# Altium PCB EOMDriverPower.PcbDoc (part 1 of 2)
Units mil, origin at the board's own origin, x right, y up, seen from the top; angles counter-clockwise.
Board outline 6400 x 9100 mil, 6 copper layers (Top Layer, GND1, PWR1, PWR2, GND2, Bottom Layer); 300 components, 184 nets, 876 pads, 174 vias.
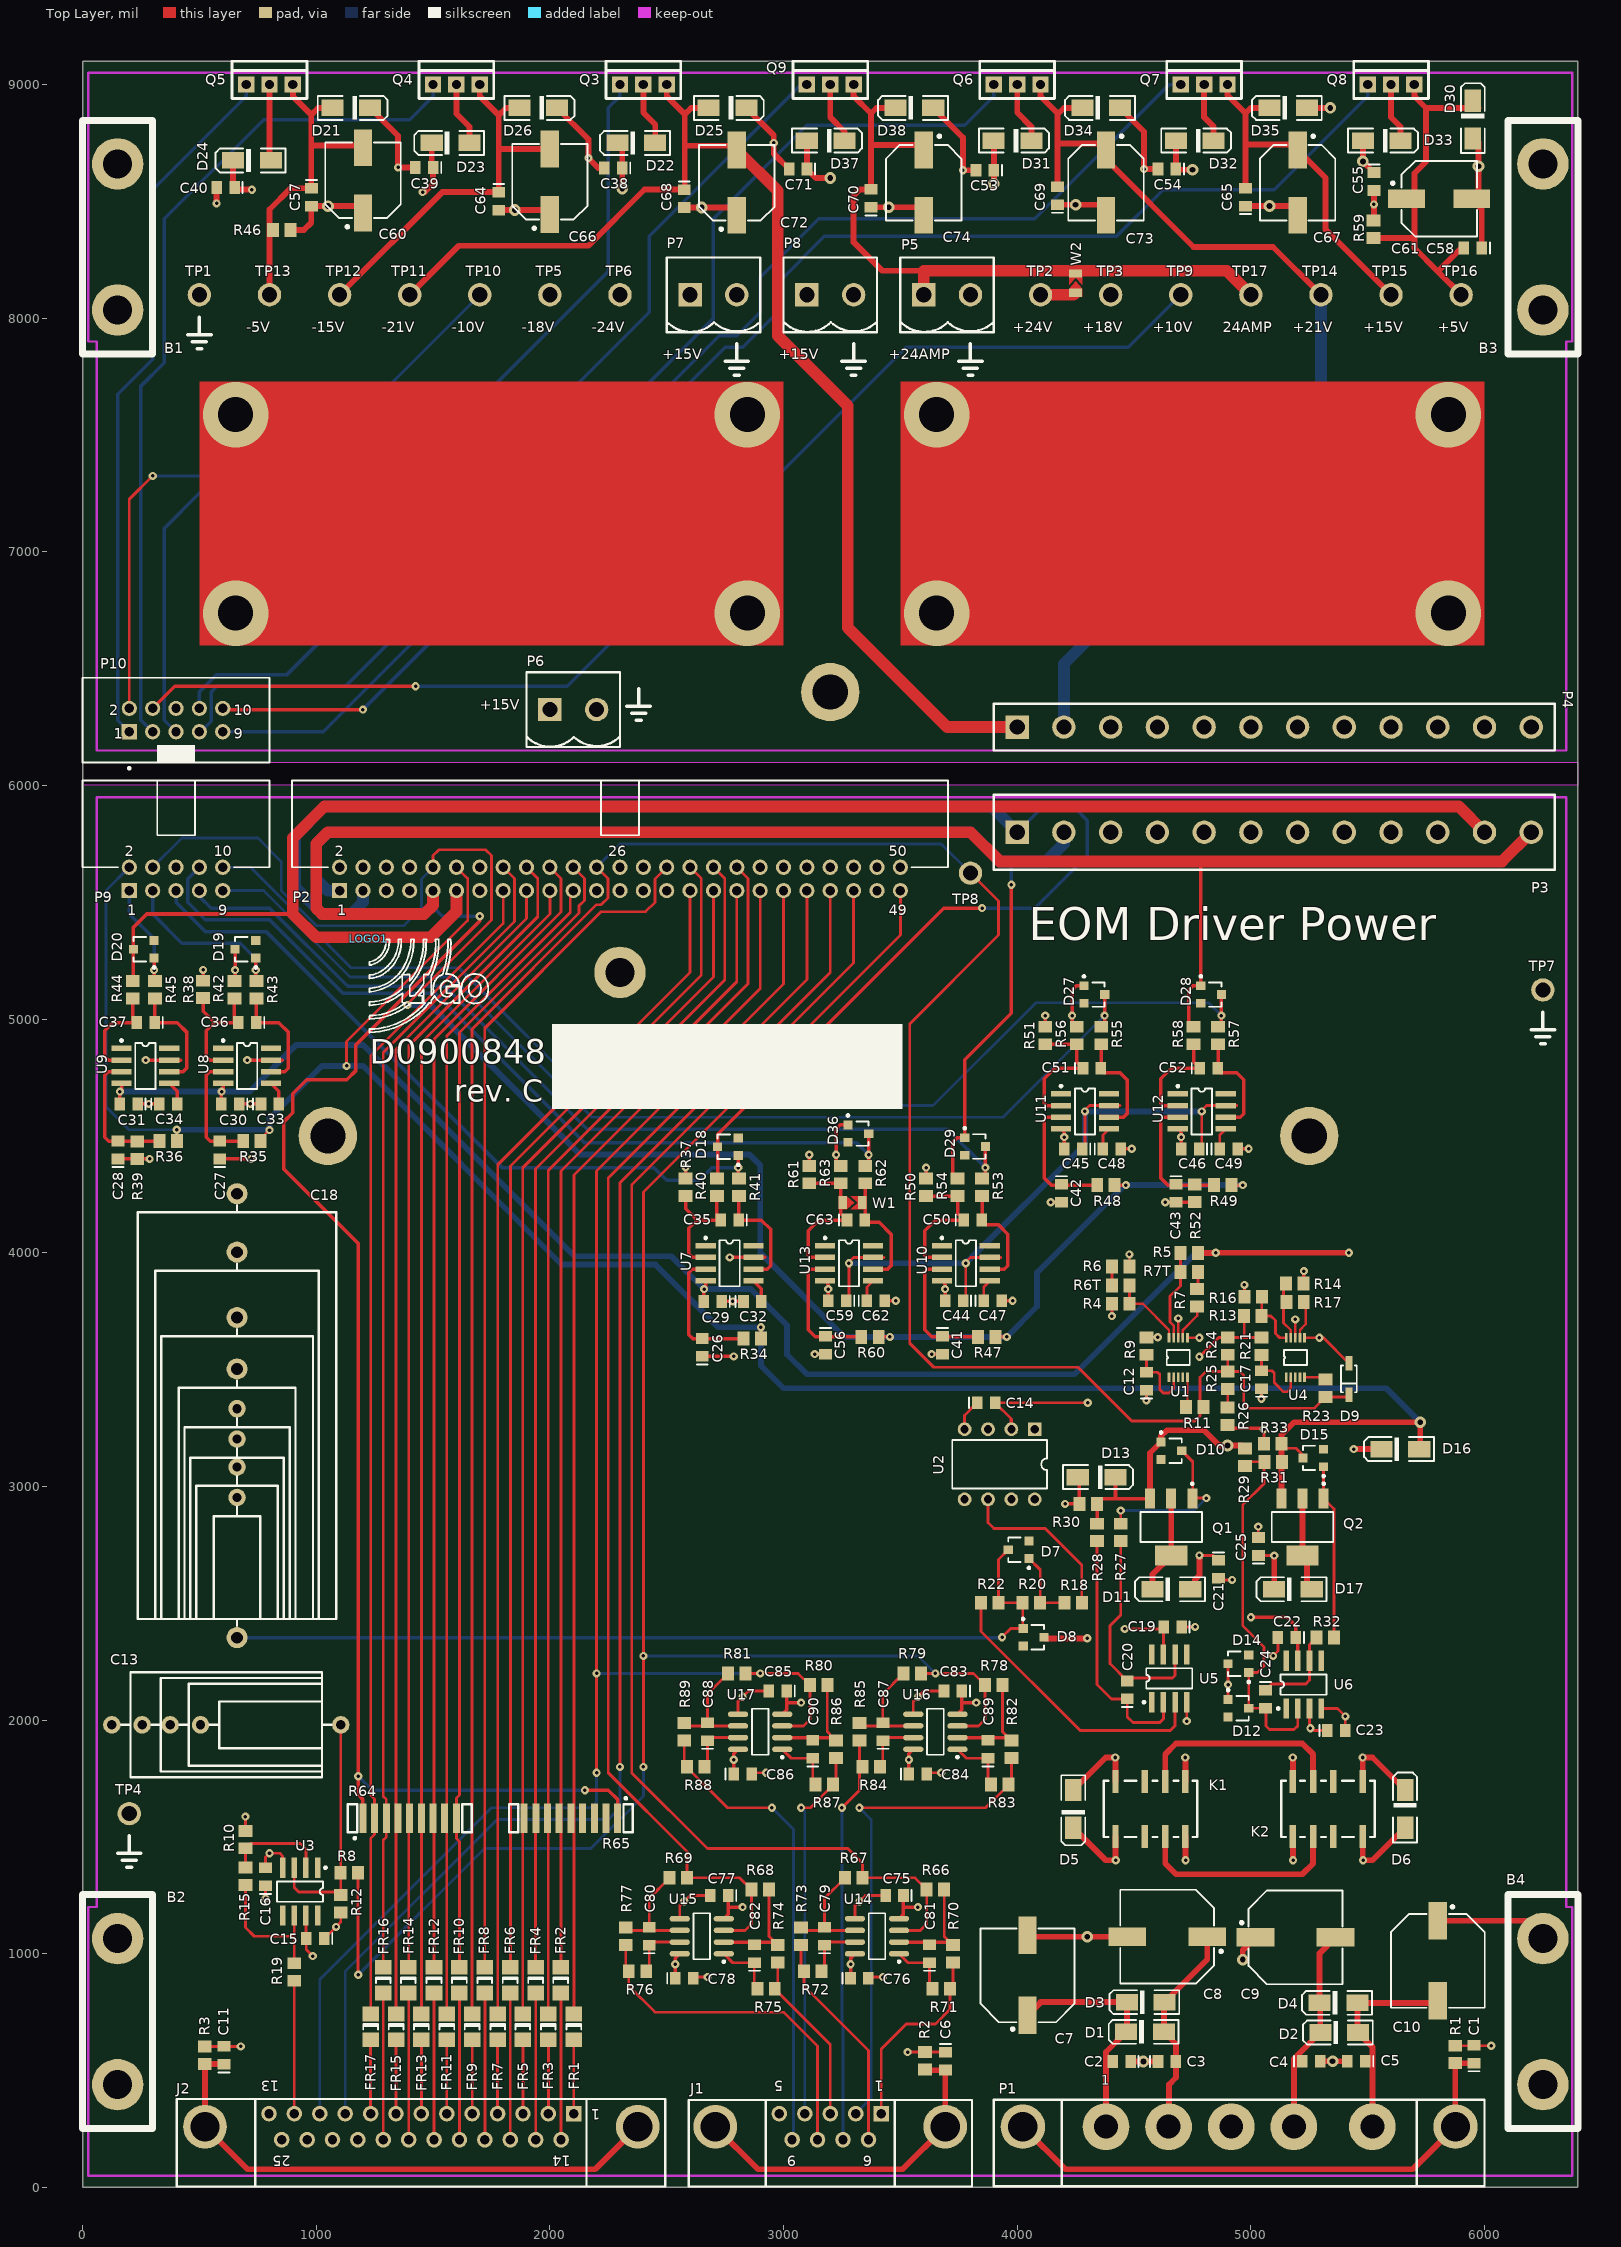
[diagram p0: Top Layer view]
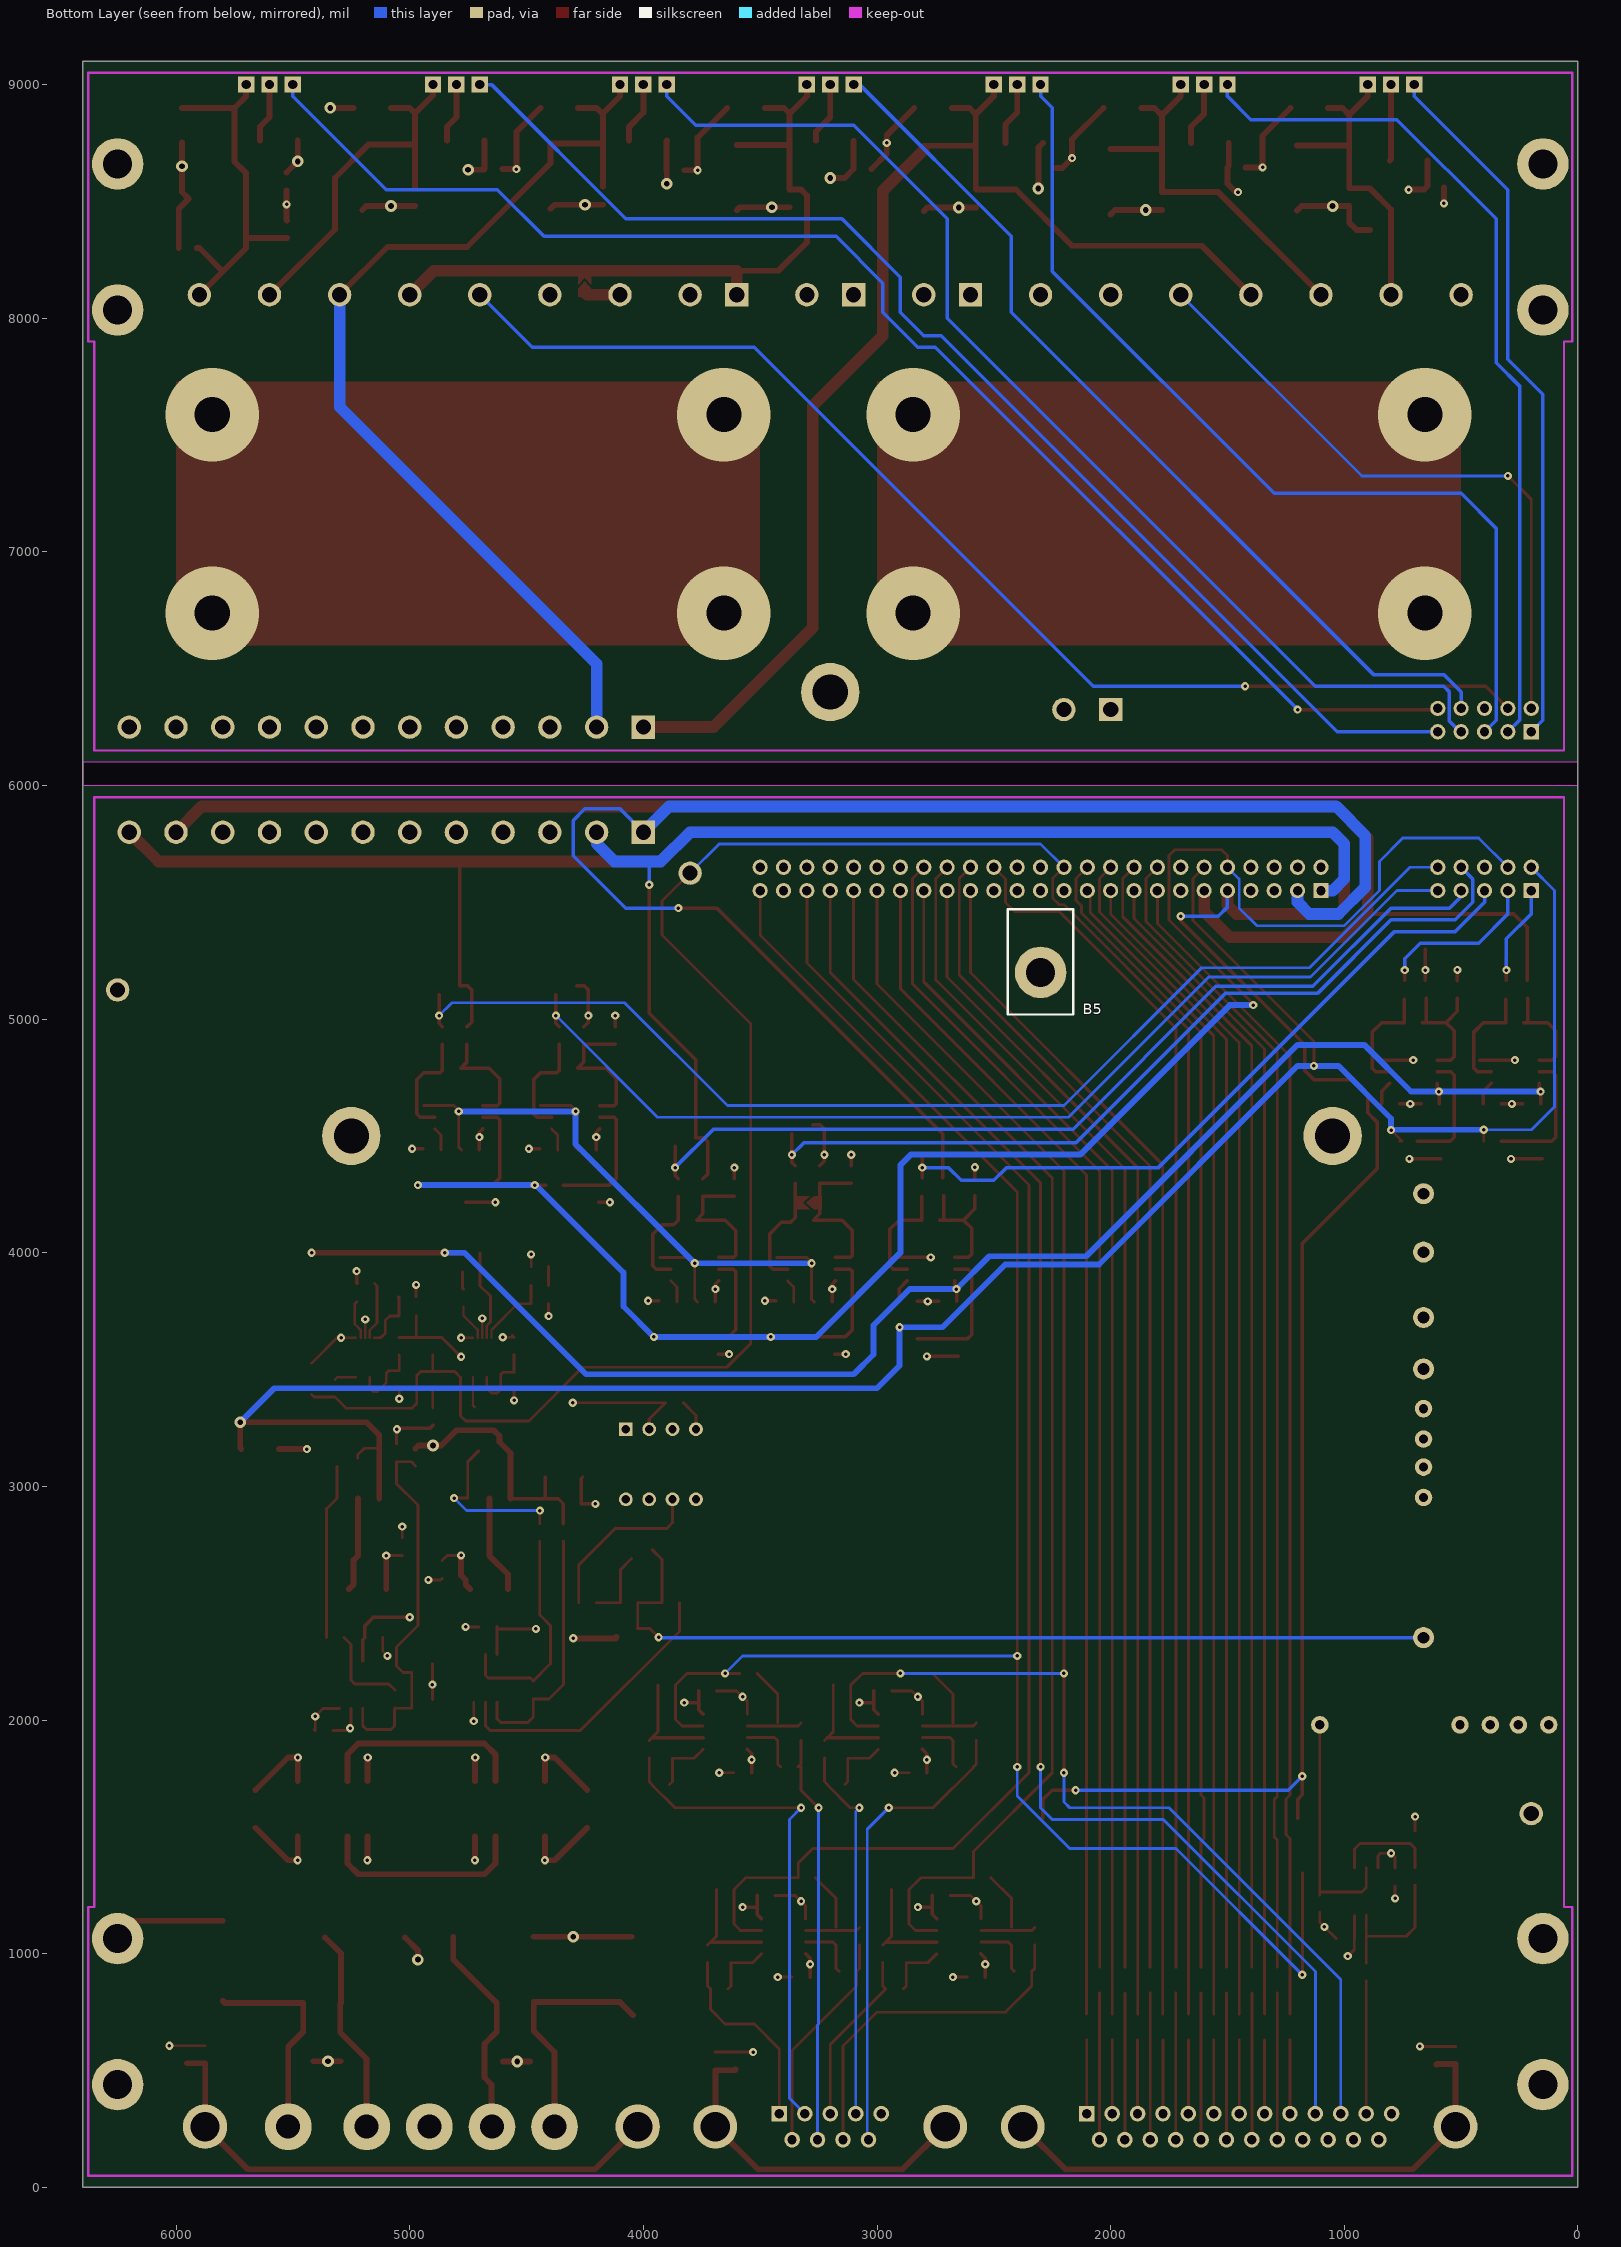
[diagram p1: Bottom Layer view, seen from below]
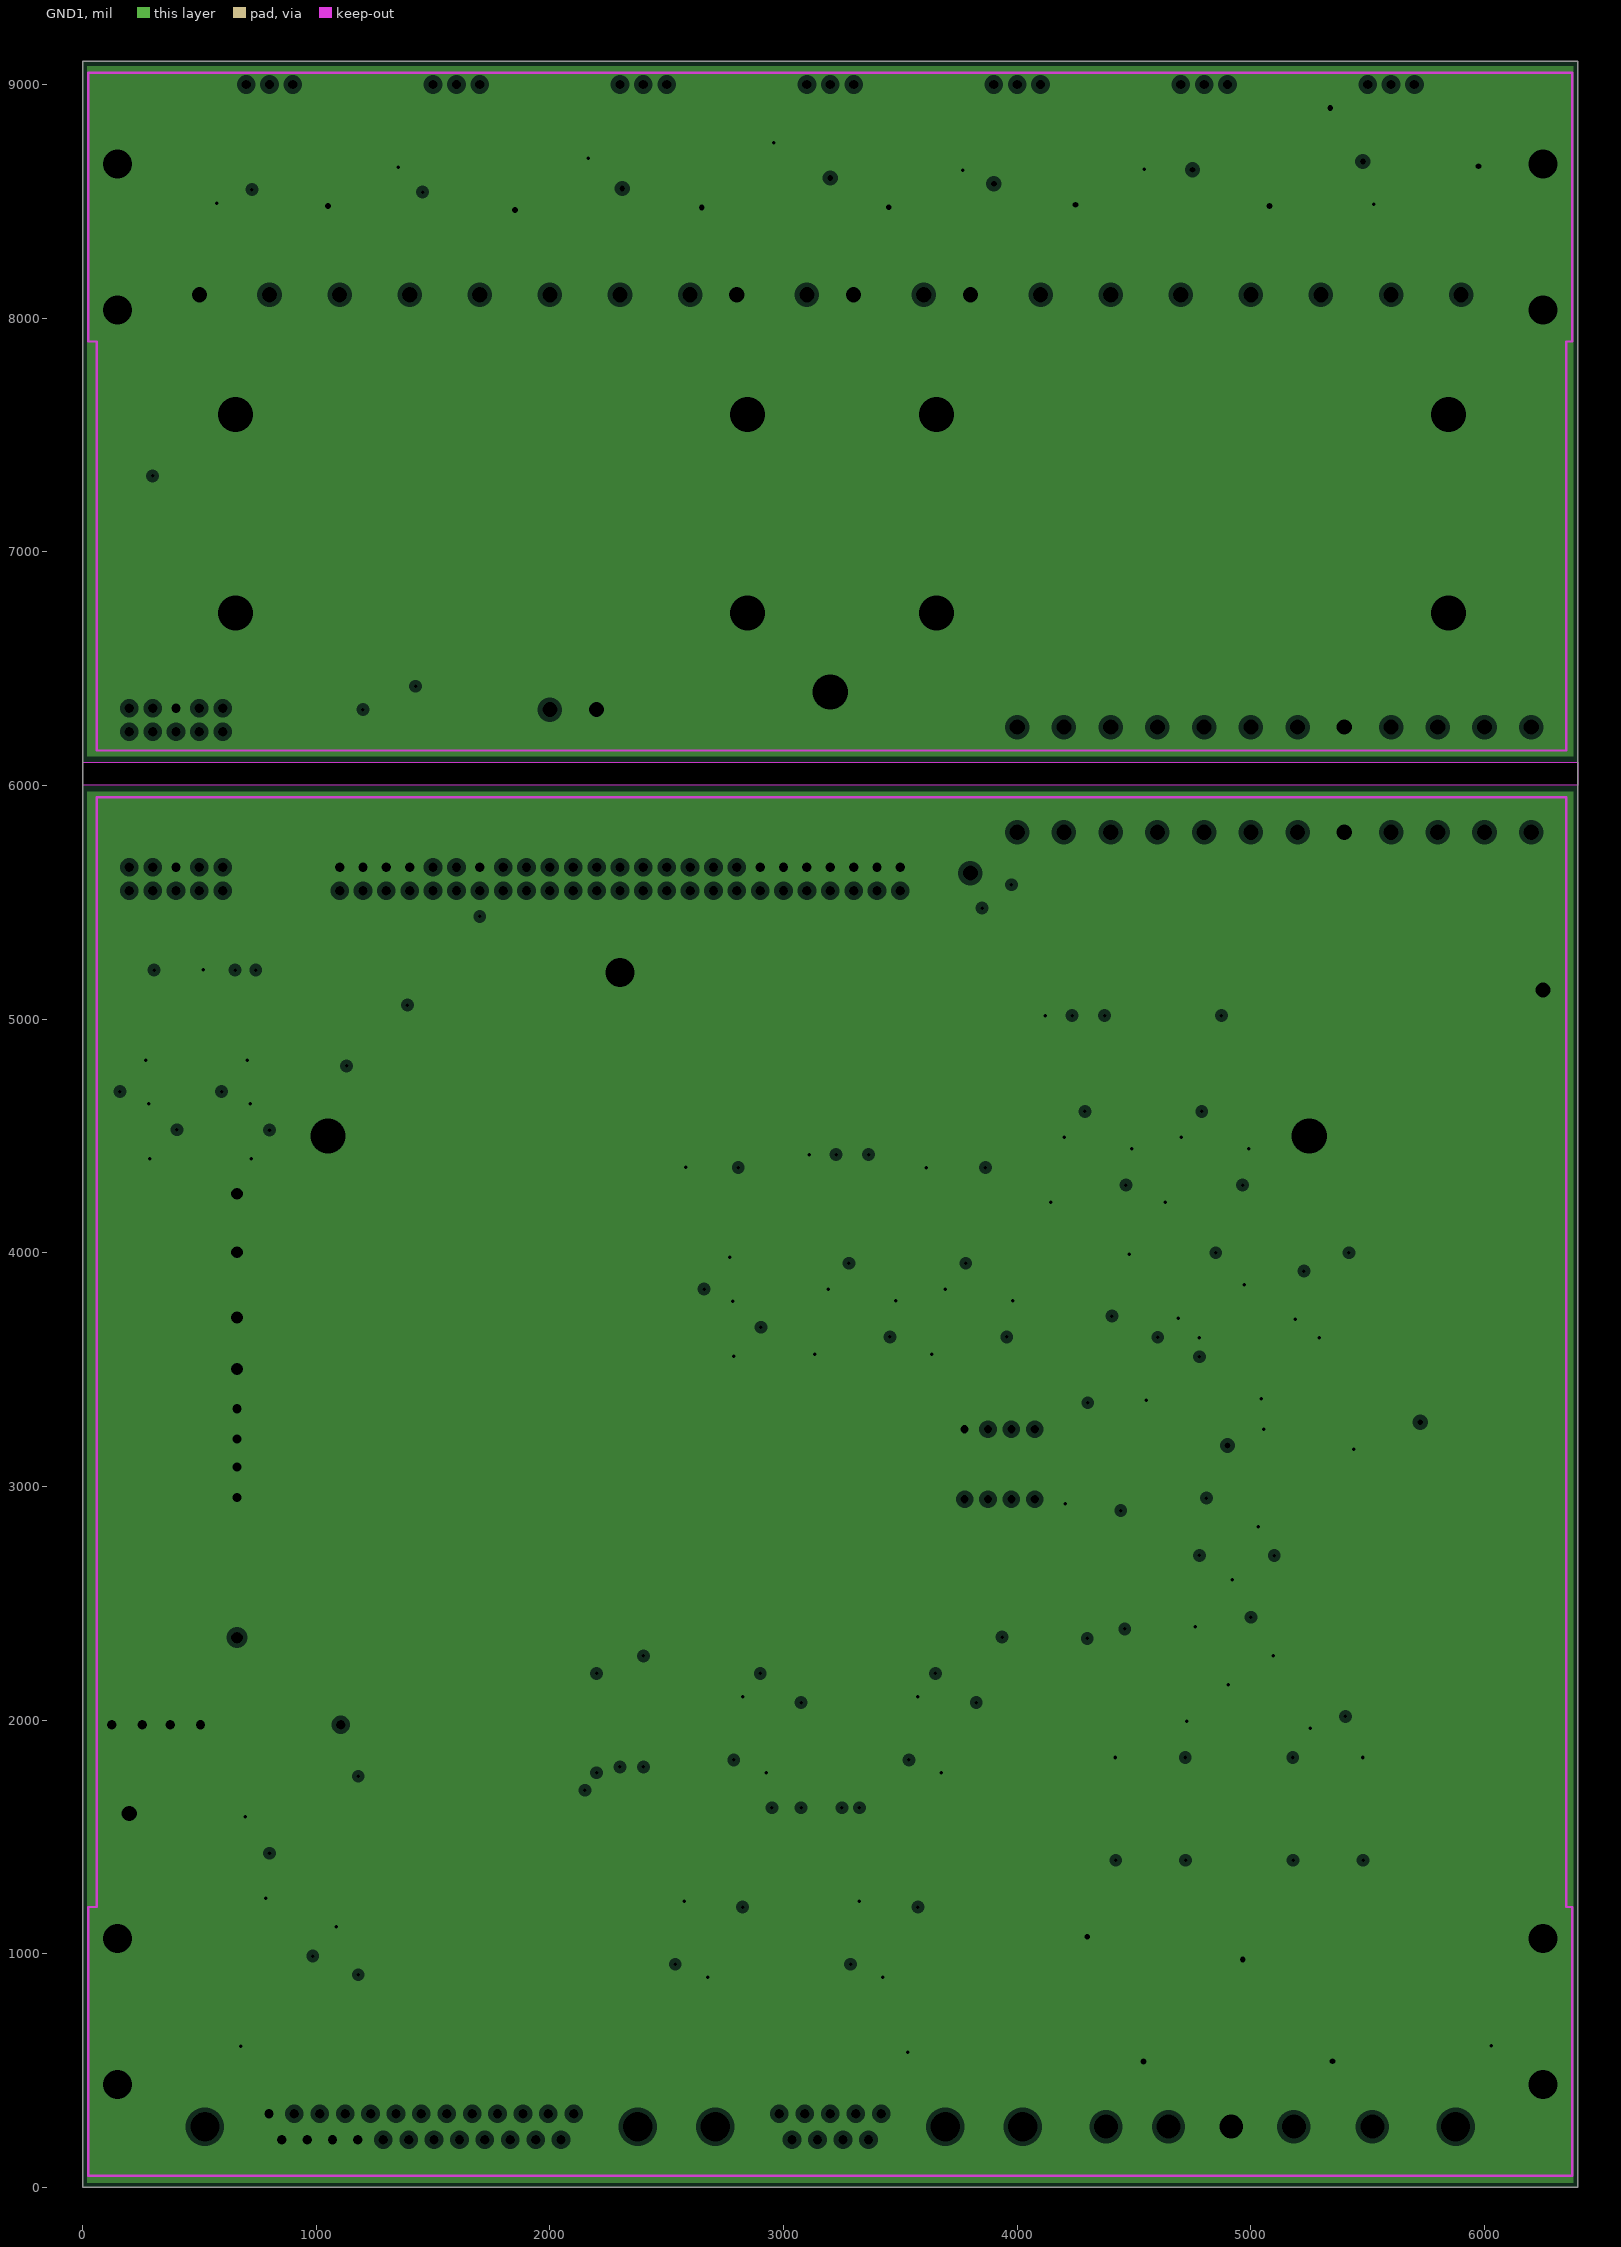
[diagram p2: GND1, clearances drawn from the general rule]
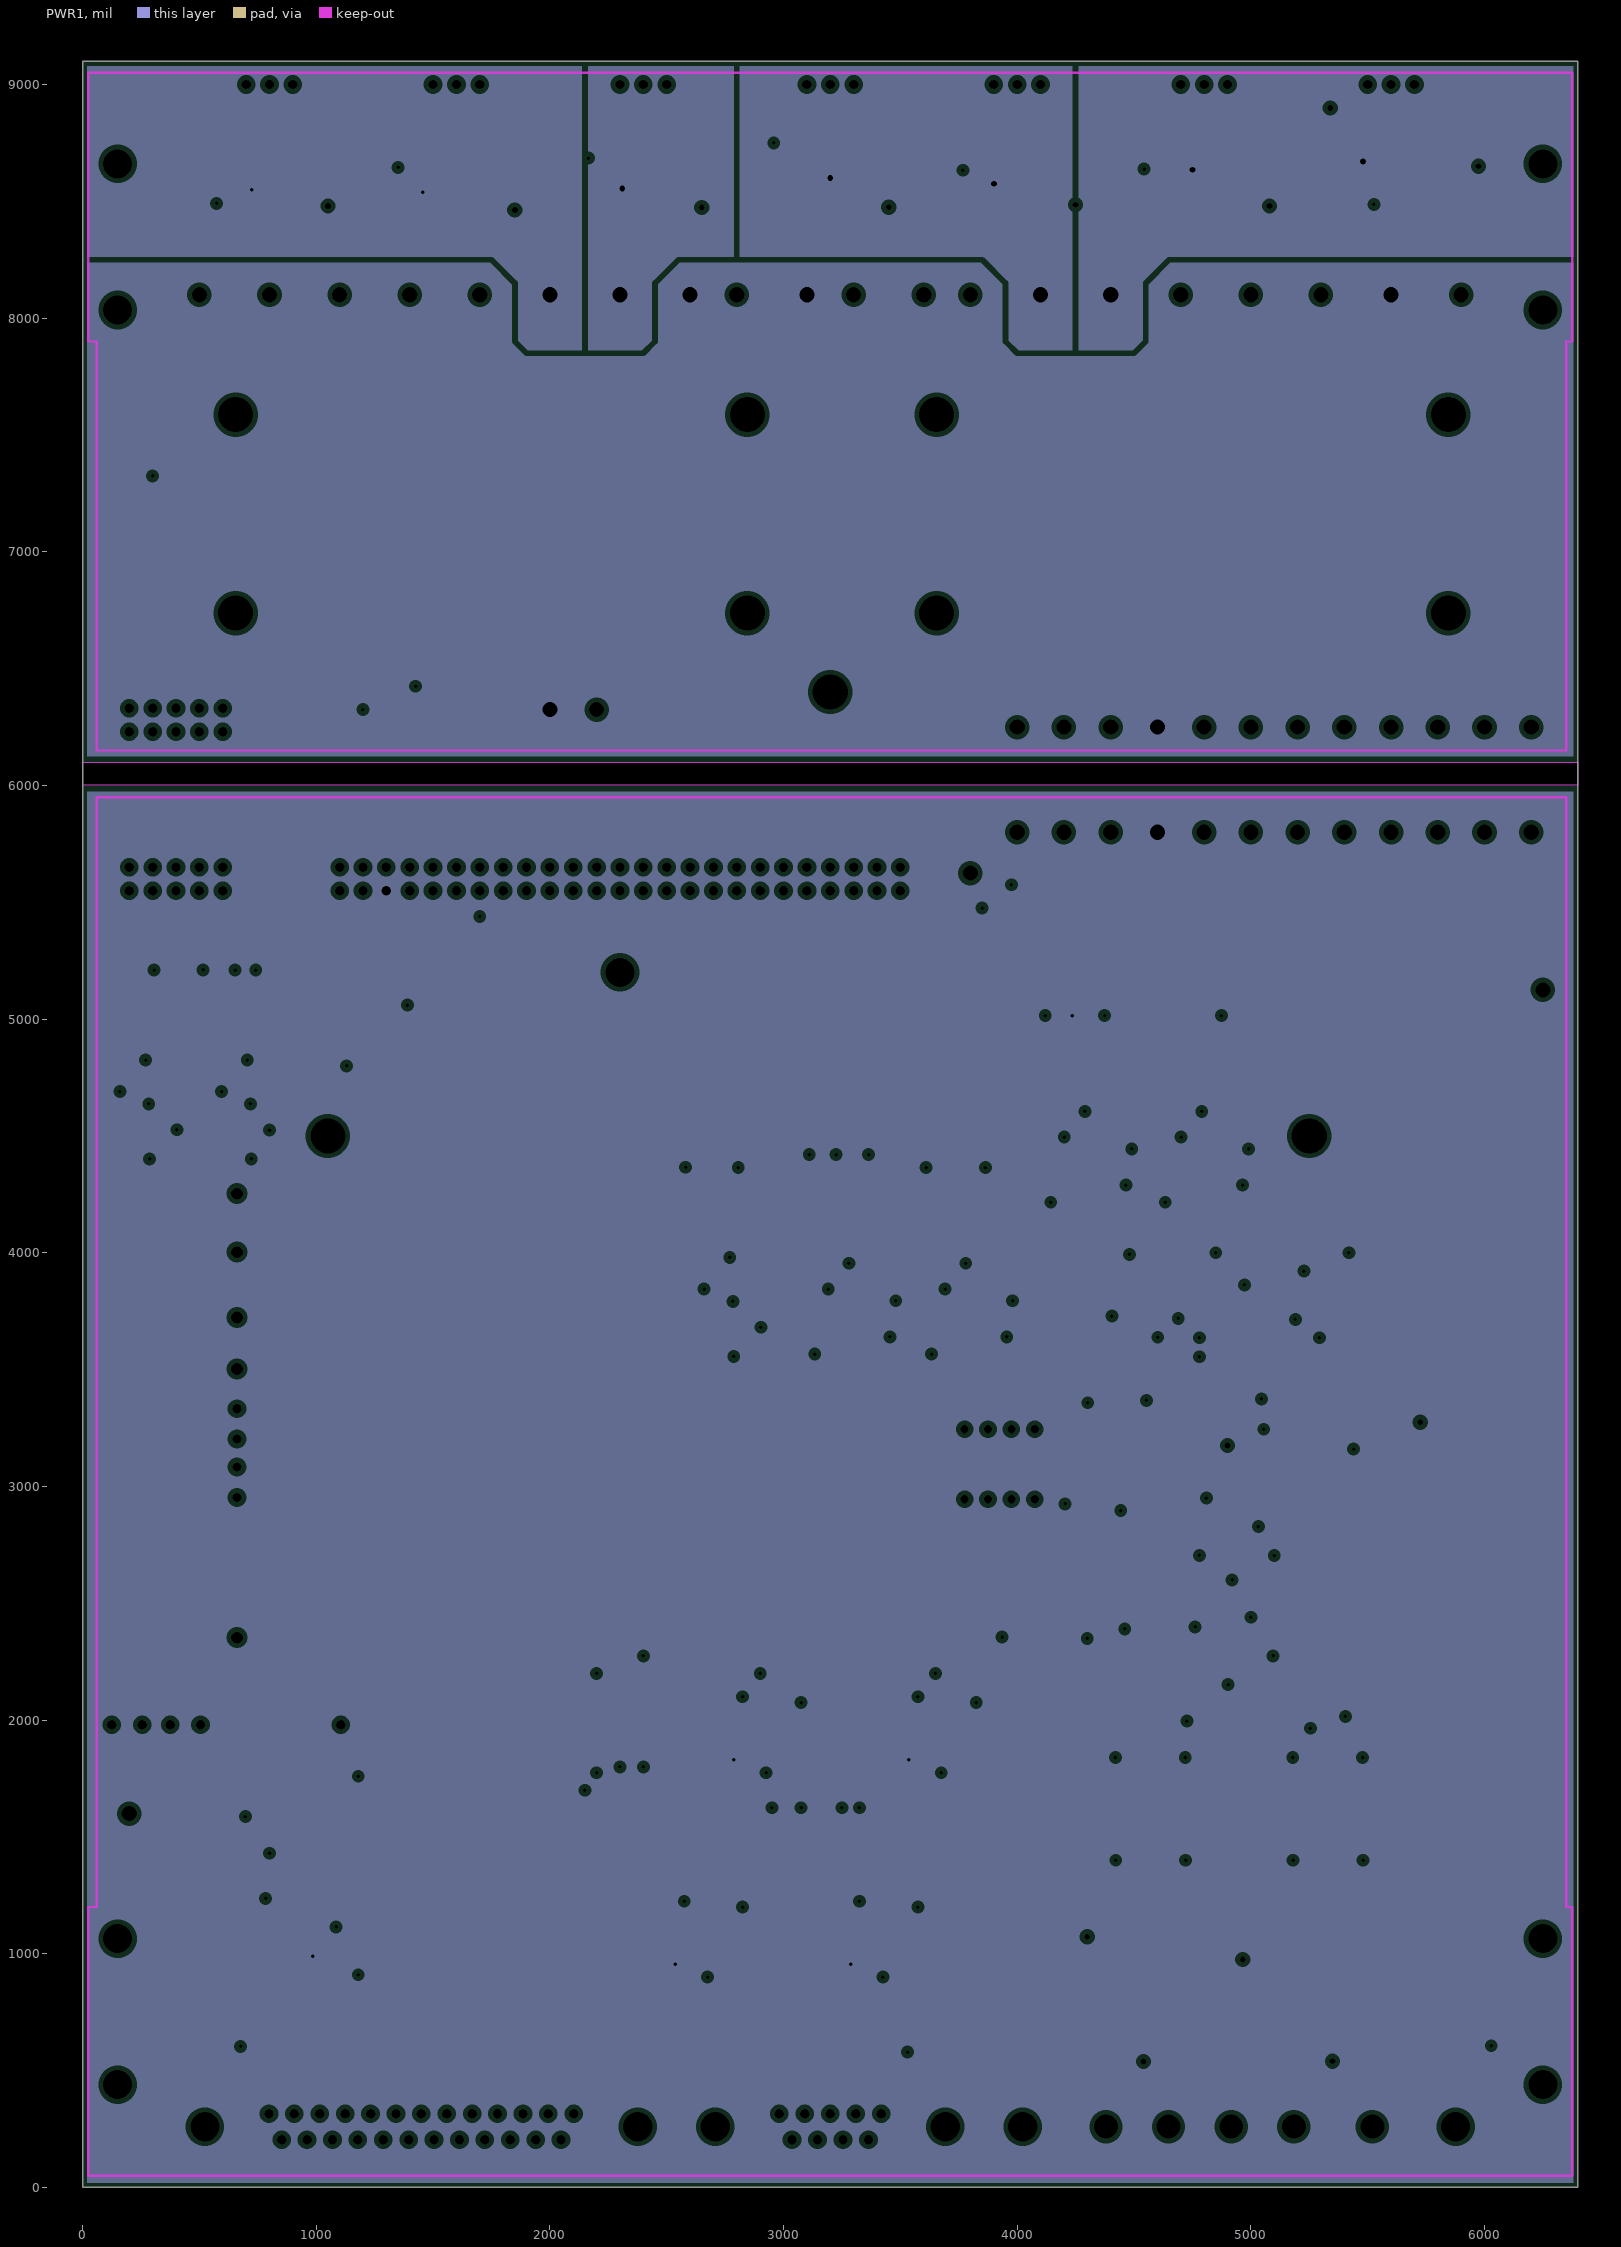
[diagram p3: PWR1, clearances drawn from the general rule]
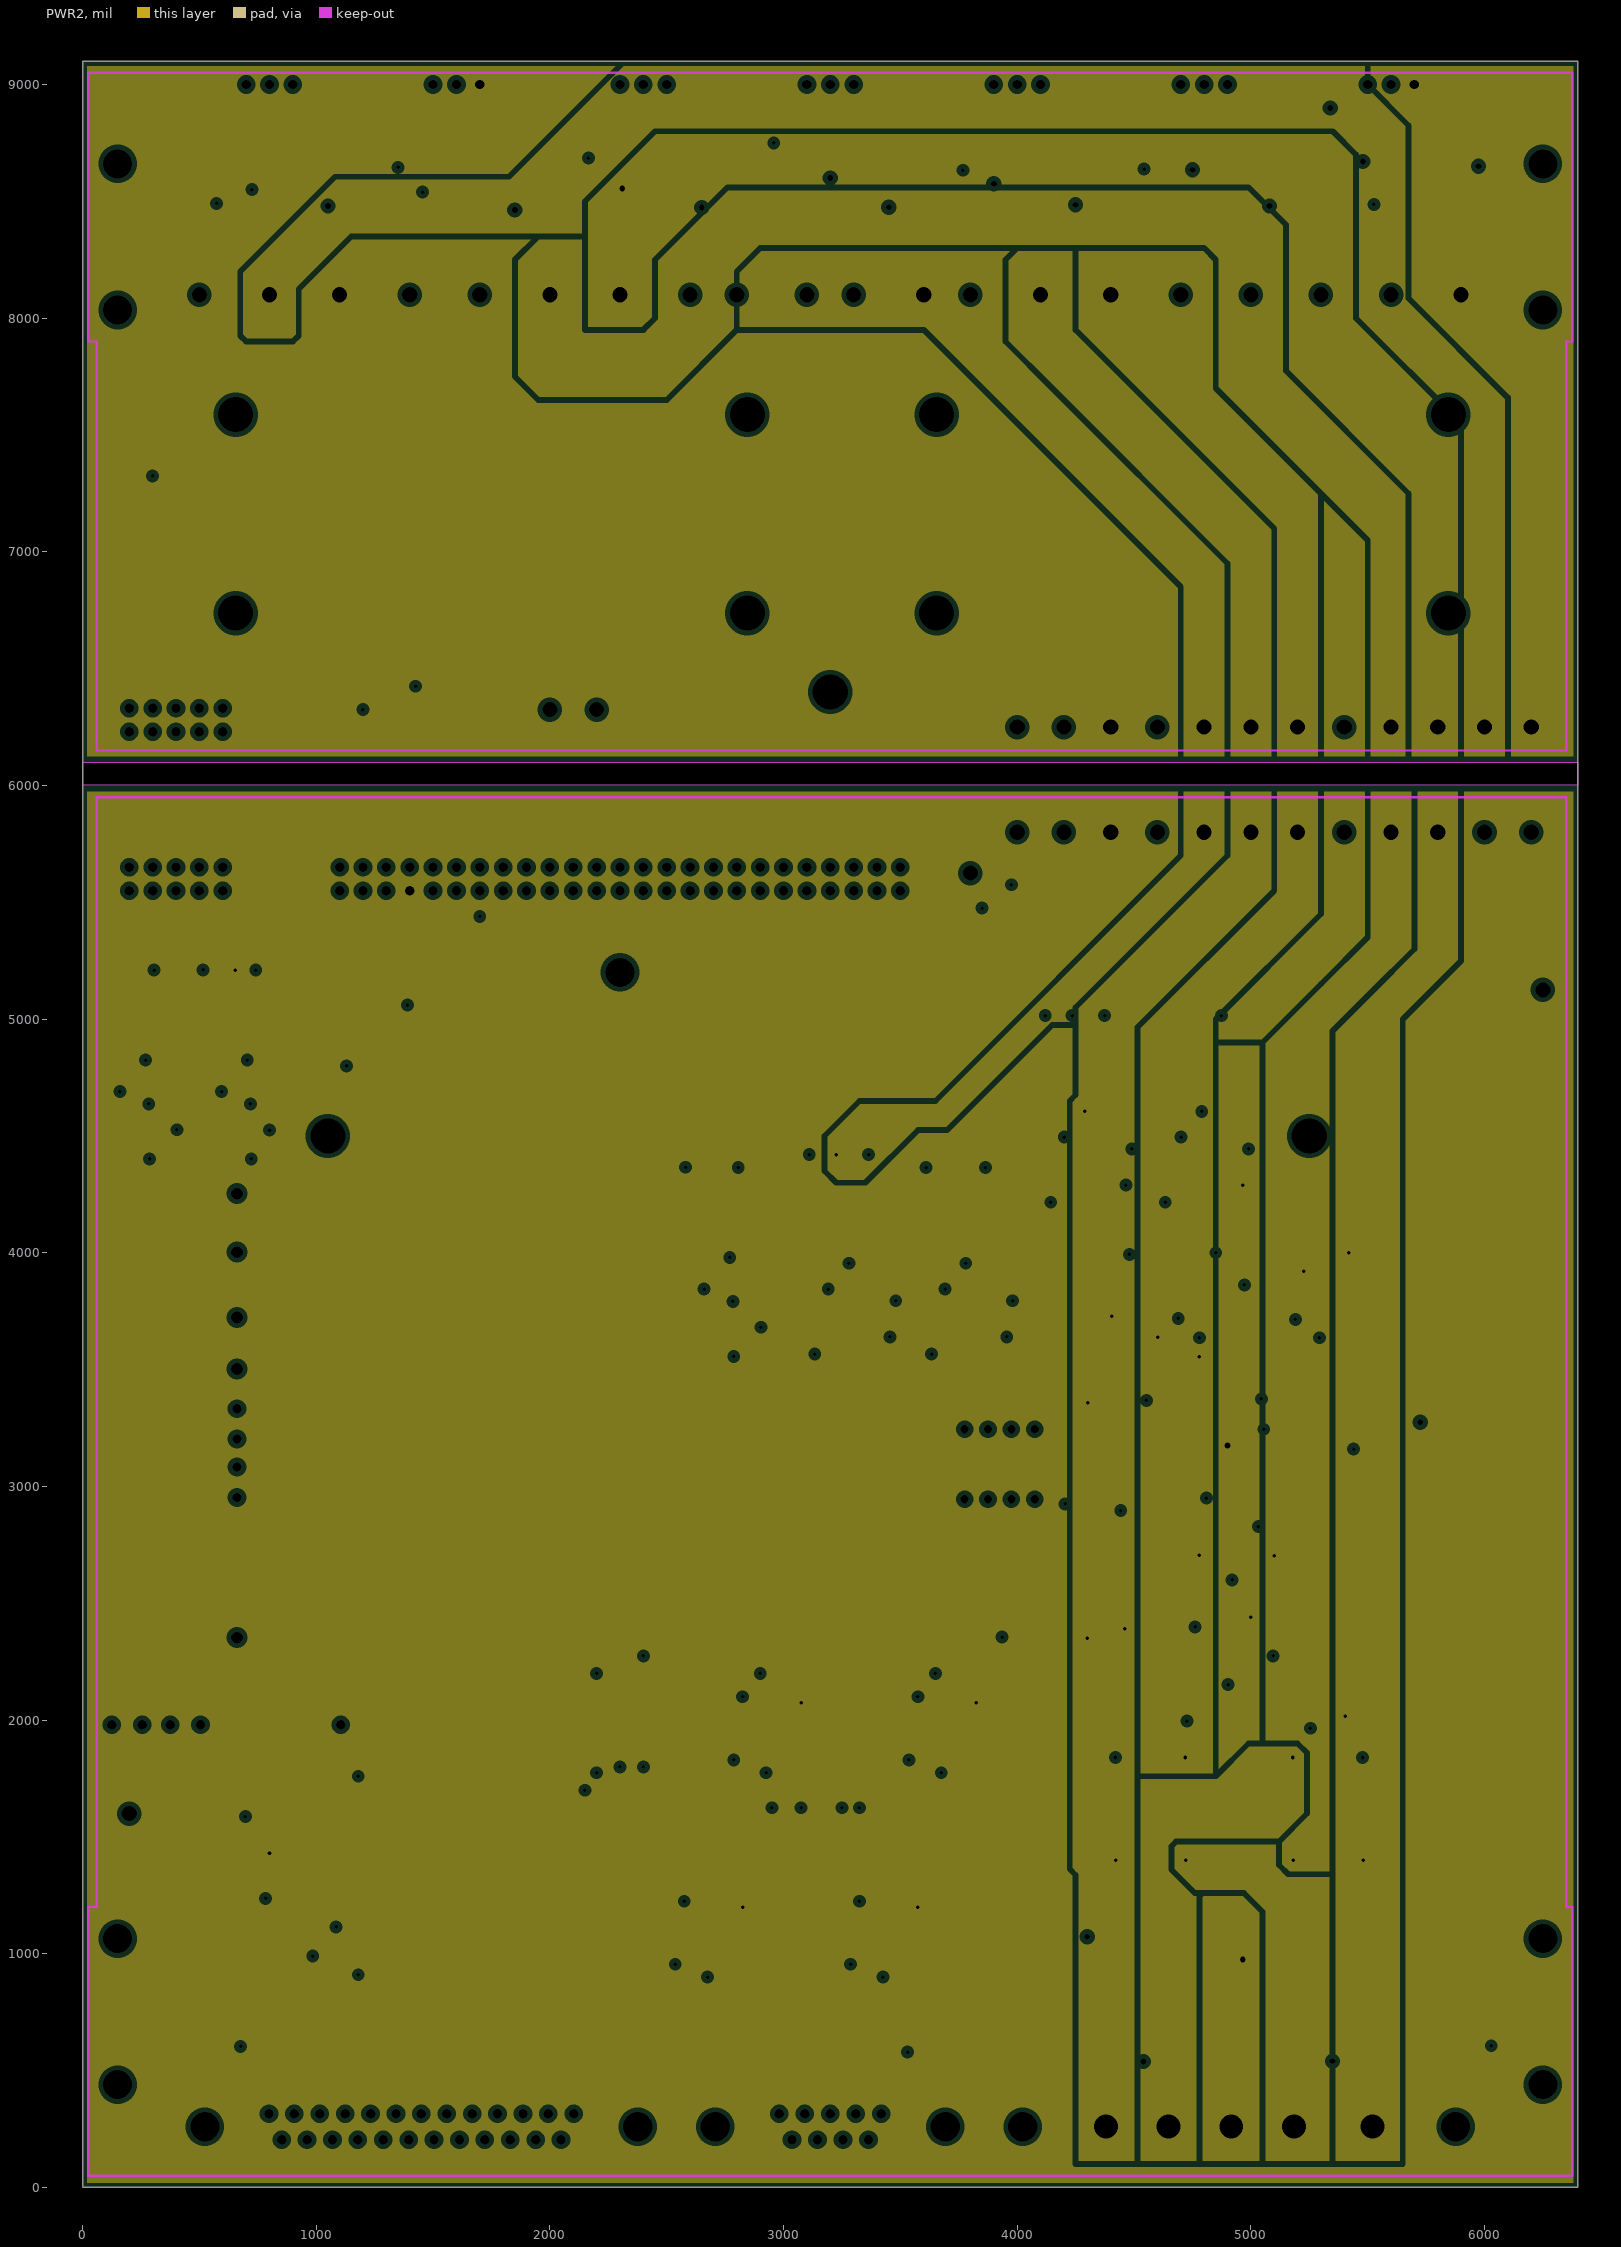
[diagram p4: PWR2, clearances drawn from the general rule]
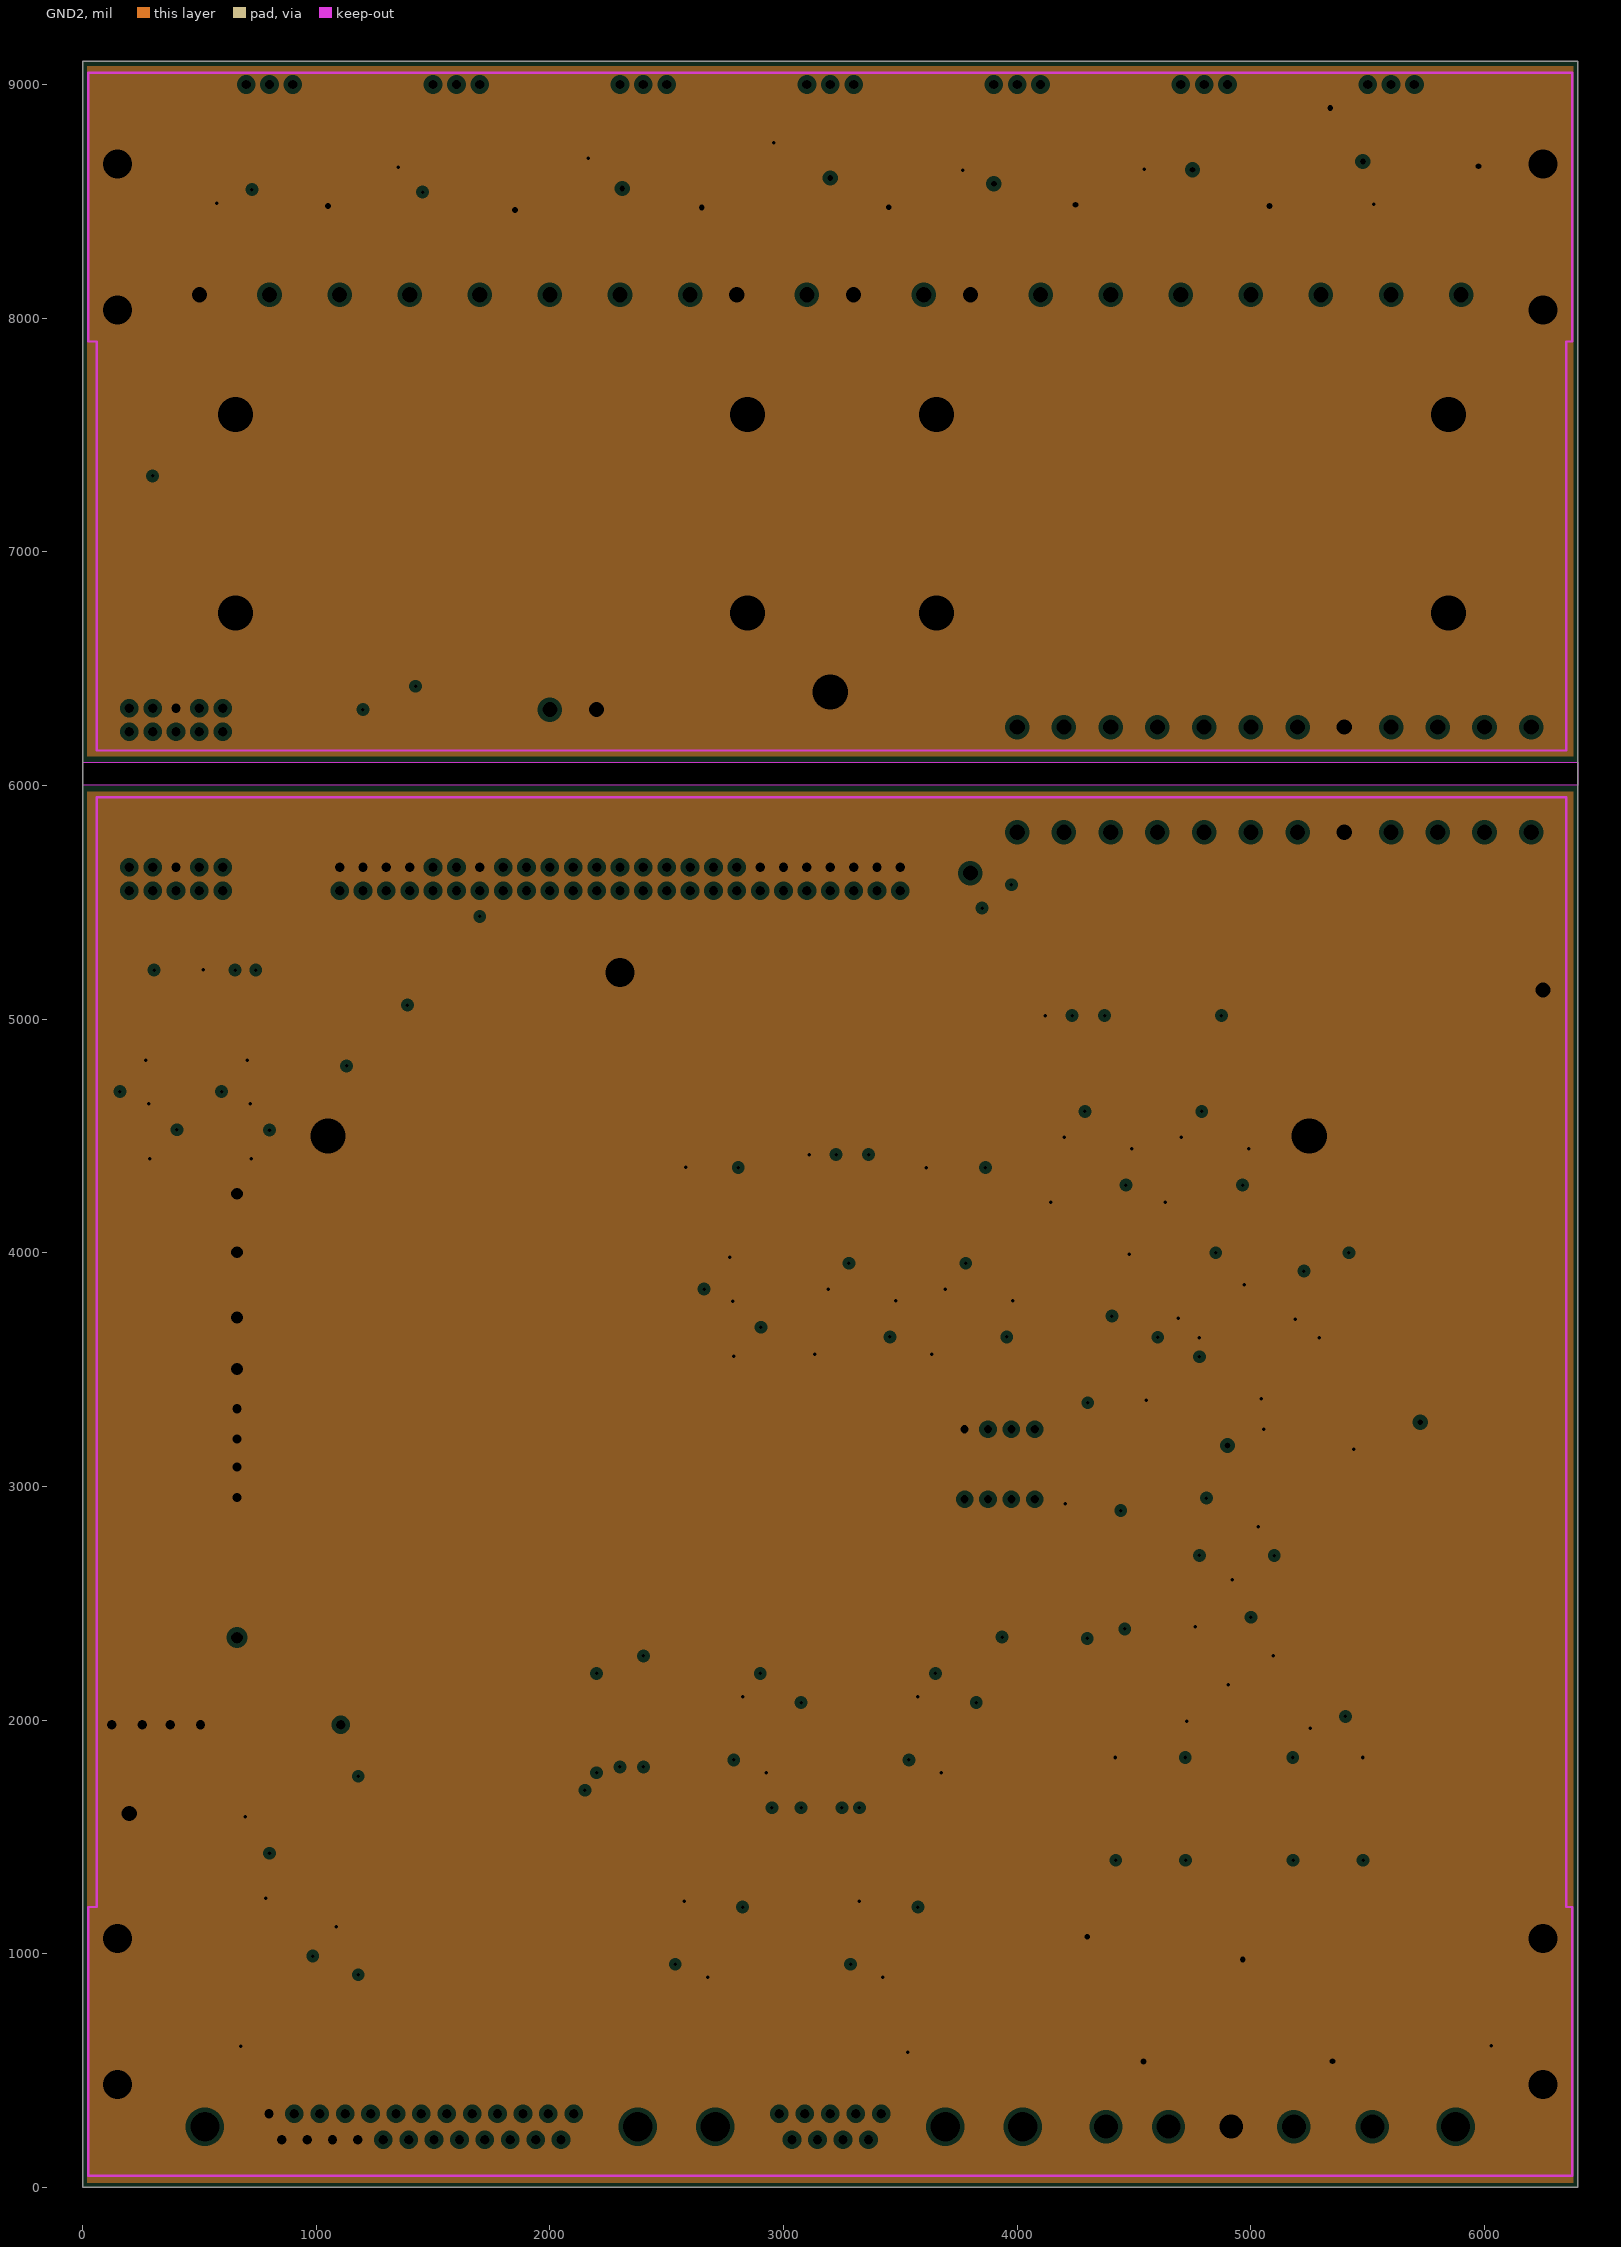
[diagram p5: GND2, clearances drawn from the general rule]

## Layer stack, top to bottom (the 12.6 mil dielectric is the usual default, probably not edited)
Top Solder: solder mask 0.4, Solder Resist, Dk 3.5
Top Layer: signal copper 1.4
Dielectric1: core 12.6, FR-4, Dk 4.8
GND1: plane copper 1.4
Dielectric2: prepreg 12.6, FR-4, Dk 4.8
PWR1: plane copper 1.4
Dielectric4: core 12.6, FR-4, Dk 4.8
PWR2: plane copper 1.4
Dielectric5: prepreg 12.6, FR-4, Dk 4.8
GND2: plane copper 1.4
Dielectric3: core 12.6, FR-4, Dk 4.8
Bottom Layer: signal copper 1.4
Bottom Solder: solder mask 0.4, Solder Resist, Dk 3.5

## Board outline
0,0 0,9100 6400,9100 6400,0
cut-out: 0,6000 0,6100 6400,6100 6400,6000

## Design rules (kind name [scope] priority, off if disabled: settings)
Clearance Clearance_1 [(HasFootprint('MSOP10'))] p1: gap=8
Clearance [All] p2: gap=9.68
FabricationTestPointUsage TestPointUsage [All] p1: valid=0 allowmultiple=FALSE
FabricationTestpoint Testpoint [All] p1: side=3 testpointundercomponent=TRUE minsize=40 maxsize=100 preferedsize=60 minholesize=0 maxholesize=40 preferedholesize=32 testpointgrid=1 allowsidetop=TRUE allowsidebottom=TRUE usegrid=TRUE gridtolerance=0.01
HoleSize [All] p1: absolutevalues=TRUE maxlimit=250 minlimit=15 maxpercent=80.000 minpercent=20.000
MinimumAnnularRing MinimumAnnularRingPad [IsPad] p1: minimumring=12
MinimumAnnularRing [All] p2: minimumring=10
MinimumSolderMaskSliver [All] p1: minsoldermaskwidth=5
PlaneClearance [All] p1: clearance=20
PlaneConnect [All] p1: planeconnectstyle=Relief reliefexpansion=20 reliefentries=4 reliefconductorwidth=10 reliefairgap=10
PolygonConnect [All] p1: connectstyle=Relief reliefconductorwidth=10 reliefentries=4 polygonreliefangle="90 Angle" airgapwidth=10
RoutingVias [All] p1: holewidth=15 width=35 viastyle="Through Hole" minholewidth=15 minwidth=35 maxholewidth=150 maxwidth=400
SilkToSilkClearance [All] p1: silktosilkclearance=8
SilkToSolderMaskClearance SilkscreenOverComponentPads [IsPad] p1: minsilkscreentomaskgap=0 clearancetoexposedcopper=TRUE
SolderMaskExpansion [All] p1: expansion=4
Width [All] p1: maxlimit=100 minlimit=8 preferedwidth=10
22 further rules are at their usual default settings.

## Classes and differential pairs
component class EOMDriverPower3: C6 C11 C13 C15 C16 C75 C76 C77 C78 C79 C80 C81 C82 C83 C84 C85 C86 C87 C88 C89 C90 FR1 FR2 FR3 FR4 FR5 FR6 FR7 FR8 FR9 FR10 FR11 FR12 FR13 FR14 FR15 FR16 FR17 J1 J2 P2 R2 R3 R8 R10 R12 R15 R19 R64 R65 R66 R67 R68 R69 R70 R71 R72 R73 R74 R75 R76 R77 R78 R79 R80 R81 R82 R83 R84 R85 R86 R87 R88 R89 U3 U14 U15 U16 U17
component class EOMDriverPower1: B1 B2 B3 B4 C1 C2 C3 C4 C5 C7 C8 C9 C10 C12 C14 C17 C18 C19 C20 C21 C22 C23 C24 C25 D1 D2 D3 D4 D5 D6 D7 D8 D9 D10 D11 D12 D13 D14 D15 D16 D17 E1 E2 E3 H1 H2 H3 H4 H5 H6 H7 H8 H9 H10 H11 H12 H13 K1 K2 LOGO1 P1 P3 P4 Q1 Q2 R1 R4 R5 R6 R6T R7 R7T R9 R11 R13 R14 R16 R17 R18 R20 R21 R22 R23 R24 R25 R26 R27 R28 R29 R30 R31 R32 R33 TP1 TP2 TP3 TP4 TP5 TP6 TP7 TP8 TP9 TP10 U1 U2 U4 U5 U6
component class EOMDriverPower2: C26 C27 C28 C29 C30 C31 C32 C33 C34 C35 C36 C37 C38 C39 C40 C41 C42 C43 C44 C45 C46 C47 C48 C49 C50 C51 C52 C53 C54 C55 C56 C57 C58 C59 C60 C61 C62 C63 C64 C65 C66 C67 C68 C69 C70 C71 C72 C73 C74 D18 D19 D20 D21 D22 D23 D24 D25 D26 D27 D28 D29 D30 D31 D32 D33 D34 D35 D36 D37 D38 P5 P6 P7 P8 P9 P10 Q3 Q4 Q5 Q6 Q7 Q8 Q9 R34 R35 R36 R37 R38 R39 R40 R41 R42 R43 R44 R45 R46 R47 R48 R49 R50 R51 R52 R53 R54 R55 R56 R57 R58 R59 R60 R61 R62 R63 TP11 TP12 TP13 TP14 TP15 TP16 TP17 U7 U8 U9 U10 U11 U12 U13 W1 W2

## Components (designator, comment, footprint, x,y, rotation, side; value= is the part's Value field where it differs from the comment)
B1 "Bracket" Bracket-RA_708 150,8660 r180 top locked
B2 "Bracket" Bracket-RA_708 150,440 r0 top locked
B3 "Bracket" Bracket-RA_708 6250,8660 r180 top locked
B4 "Bracket" Bracket-RA_708 6250,440 r0 top locked
C1 "100n" CC2013-0805 5955,570 r90 top
C2 "100n" CC2013-0805 4447,539 r180 top
C3 "100n" CC2013-0805 4641,539 r0 top
C4 "100n" CC2013-0805 5258,540 r0 top
C5 "100n" CC2013-0805 5451,540 r180 top
C6 "100n" CC2013-0805 3693,541 r270 top
C7 "100u" AC103-041/G 4044,908 r90 top
C8 "100u" AC103-041/G 4642,1073 r180 top
C9 "100u" AC103-041/G 5191,1070 r0 top
C10 "100u" AC103-041/G 5800,970 r270 top
C11 "100n" CC2013-0805 605,565 r90 top
C12 "100n" CC2013-0805 4553,3450 r90 top
C13 "1u" CA-ALL4 1105,1980 r180 top
C14 "100n" CC2013-0805 3867,3358 r0 top
C15 "100n" CC2013-0805 996,1065 r180 top
C16 "100n" CC2013-0805 783,1329 r90 top
C17 "100n" CC2013-0805 5045,3457 r90 top
C18 "20u" CA-ALL8 661,2353 r90 top
C19 "100n" CC2013-0805 4665,2399 r180 top
C20 "100p" CC2013-0805 4471,2129 r90 top
C21 "100n" CC2013-0805 4861,2645 r270 top
C22 "100n" CC2013-0805 5154,2353 r180 top
C23 "100n" CC2013-0805 5366,1956 r0 top
C24 "470p" CC2013-0805 5063,2090 r270 top
C25 "100n" CC2013-0805 5032,2743 r90 top
C26 "100n" CC2013-0805 2652,3595 r90 top
C27 "100n" CC2013-0805 587,4440 r90 top
C28 "100n" CC2013-0805 152,4440 r90 top
C29 "100n" CC2013-0805 2697,3792 r180 top
C30 "100n" CC2013-0805 632,4637 r180 top
C31 "100n" CC2013-0805 197,4637 r180 top
C32 "68p" CC2013-0805 2867,3792 r0 top
C33 "68p" CC2013-0805 802,4637 r0 top
C34 "68p" CC2013-0805 367,4637 r0 top
C35 "47p" CC2013-0805 2770,4140 r180 top
C36 "47p" CC2013-0805 705,4985 r180 top
C37 "47p" CC2013-0805 270,4985 r180 top
C38 "100n" CC2013-0805 2271,8643 r180 top
C39 "100n" CC2013-0805 1462,8645 r180 top
C40 "100n" CC2013-0805 612,8559 r180 top
C41 "100n" CC2013-0805 3680,3605 r270 top
C42 "100n" CC2013-0805 4190,4255 r270 top
C43 "100n" CC2013-0805 4680,4255 r270 top
C44 "100n" CC2013-0805 3730,3795 r180 top
C45 "100n" CC2013-0805 4240,4445 r180 top
C46 "100n" CC2013-0805 4740,4445 r180 top
C47 "68p" CC2013-0805 3895,3795 r0 top
C48 "68p" CC2013-0805 4405,4445 r0 top
C49 "68p" CC2013-0805 4905,4445 r0 top
C50 "47p" CC2013-0805 3810,4140 r0 top
C51 "47p" CC2013-0805 4320,4790 r0 top
C52 "47p" CC2013-0805 4820,4790 r0 top
C53 "100n" CC2013-0805 3862,8633 r180 top
C54 "100n" CC2013-0805 4641,8638 r180 top
C55 "100n" CC2013-0805 5527,8585 r270 top
C56 "100n" CC2013-0805 3180,3605 r270 top
C57 "100n" CC2013-0805 979,8518 r270 top
C58 "100n" CC2013-0805 5950,8300 r180 top
C59 "100n" CC2013-0805 3230,3795 r180 top
C60 "330u" AC083-033/F 1200,8590 r90 top
C61 "330u" AC083-033/F 5806,8511 r0 top
C62 "68p" CC2013-0805 3395,3795 r0 top
C63 "47p" CC2013-0805 3310,4140 r0 top
C64 "100n" CC2013-0805 1781,8501 r270 top
C65 "100n" CC2013-0805 4977,8518 r90 top
C66 "100u" AC083-033/F 2000,8584 r90 top
C67 "100u" AC083-033/F 5200,8580 r270 top
C68 "100n" CC2013-0805 2575,8512 r270 top
C69 "100n" CC2013-0805 4172,8524 r90 top
C70 "100n" CC2013-0805 3374,8513 r90 top
C71 "100n" CC2013-0805 3062,8638 r180 top
C72 "100u" AC083-033/F 2800,8580 r90 top
C73 "100u" AC083-033/F 4380,8580 r270 top
C74 "100u" AC083-033/F 3600,8580 r270 top
C75 "100n" CC2013-0805 3475,1250 r180 top
C76 "100n" CC2013-0805 3325,895 r0 top
C77 "100n" CC2013-0805 2725,1250 r180 top
C78 "100n" CC2013-0805 2575,895 r0 top
C79 "33p" CC2013-0805 3175,1075 r90 top
C80 "33p" CC2013-0805 2425,1075 r90 top
C81 "33p" CC2013-0805 3625,1000 r90 top
C82 "33p" CC2013-0805 2875,1000 r90 top
C83 "100n" CC2013-0805 3725,2125 r180 top
C84 "100n" CC2013-0805 3575,1770 r0 top
C85 "100n" CC2013-0805 2975,2125 r180 top
C86 "100n" CC2013-0805 2825,1770 r0 top
C87 "33p" CC2013-0805 3425,1950 r90 top
C88 "33p" CC2013-0805 2675,1950 r90 top
C89 "33p" CC2013-0805 3875,1875 r90 top
C90 "33p" CC2013-0805 3125,1875 r90 top
D1 "shottky diode" DO-SMA 4547,666 r180 top
D2 "shottky diode" DO-SMA 5378,663 r180 top
D3 "shottky diode" DO-SMA 4550,793 r180 top
D4 "shottky diode" DO-SMA 5375,790 r180 top
D5 "shottky diode" DO-SMA 4240,1620 r270 top
D6 "shottky diode" DO-SMA 5660,1620 r90 top
D7 "BAS16" SO-G3/C2.25 4006,2729 r90 top
D8 "BAS16" SO-G3/C2.25 4070,2355 r270 top
D9 "zener diode" DO-SOD123 5420,3460 r270 top
D10 "BAS16" SO-G3/C2.25 4660,3153 r270 top
D11 "shottky diode" DO-SMA 4660,2560 r180 top
D12 "BAS16" SO-G3/C2.25 4947,2051 r270 top
D13 "shottky diode" DO-SMA 4340,3040 r0 top
D14 "BAS16" SO-G3/C2.25 4947,2241 r90 top
D15 "BAS16" SO-G3/C2.25 5267,3122 r90 top
D16 "shottky diode" DO-SMA 5640,3160 r180 top
D17 "shottky diode" DO-SMA 5180,2560 r180 top
D18 "BAS16" SO-G3/C2.25 2762,4454 r90 top
D19 "BAS16" SO-G3/C2.25 697,5299 r90 top
D20 "BAS16" SO-G3/C2.25 262,5299 r90 top
D21 "shottky diode" DO-SMA 1150,8900 r0 top
D22 "shottky diode" DO-SMA 2370,8750 r180 top
D23 "shottky diode" DO-SMA 1575,8750 r180 top
D24 "shottky diode" DO-SMA 725,8675 r180 top
D25 "shottky diode" DO-SMA 2760,8900 r0 top
D26 "shottky diode" DO-SMA 1950,8900 r0 top
D27 "BAS16" SO-G3/C2.25 4330,5105 r270 top
D28 "BAS16" SO-G3/C2.25 4830,5105 r270 top
D29 "BAS16" SO-G3/C2.25 3820,4455 r270 top
D30 "shottky diode" DO-SMA 5950,8850 r90 top
D31 "shottky diode" DO-SMA 3980,8760 r0 top
D32 "shottky diode" DO-SMA 4760,8760 r0 top
D33 "shottky diode" DO-SMA 5560,8760 r0 top
D34 "shottky diode" DO-SMA 4360,8900 r180 top
D35 "shottky diode" DO-SMA 5160,8900 r180 top
D36 "BAS16" SO-G3/C2.25 3320,4510 r270 top
D37 "shottky diode" DO-SMA 3180,8760 r0 top
D38 "shottky diode" DO-SMA 3560,8900 r180 top
FR1 "BLM31PG121" CC3216-1206 2103,687 r270 top
FR2 "BLM31PG121" CC3216-1206 2046,887 r270 top
FR3 "BLM31PG121" CC3216-1206 1993,687 r270 top
FR4 "BLM31PG121" CC3216-1206 1939,887 r270 top
FR5 "BLM31PG121" CC3216-1206 1884,687 r270 top
FR6 "BLM31PG121" CC3216-1206 1830,887 r270 top
FR7 "BLM31PG121" CC3216-1206 1777,687 r270 top
FR8 "BLM31PG121" CC3216-1206 1721,887 r270 top
FR9 "BLM31PG121" CC3216-1206 1667,687 r270 top
FR10 "BLM31PG121" CC3216-1206 1613,887 r270 top
FR11 "BLM31PG121" CC3216-1206 1559,687 r270 top
FR12 "BLM31PG121" CC3216-1206 1504,887 r270 top
FR13 "BLM31PG121" CC3216-1206 1450,687 r270 top
FR14 "BLM31PG121" CC3216-1206 1394,887 r270 top
FR15 "BLM31PG121" CC3216-1206 1342,687 r270 top
FR16 "BLM31PG121" CC3216-1206 1287,887 r270 top
FR17 "BLM31PG121" CC3216-1206 1233,687 r270 top
J1 "DB9F" DB9F-RA 3200,260 r180 top locked
J2 "DB25F" DB25F-RA 1450,260 r180 top locked
K1 "IM07GR" RELAY_IMG 4720,1720 r270 top
K2 "IM07GR" RELAY_IMG 5180,1520 r90 top
LOGO1 "LIGO logo" LIGO_LOGO 1225,5345 r0 top
P1 "DsubPower" DSUB-PWR5-RAPLUG 4950,260 r270 top locked
P2 "09 18 150 9421" 918550x323 2300,5650 r0 top locked
P3 "TBlock_5.08_12" TBLOCK-5.08-12 5100,5800 r0 top locked
P4 "TBlock_5.08_12" TBLOCK-5.08-12 5100,6250 r0 top locked
P5 "TBlock_5.08_2" TBLOCK-5.08-2 3700,8100 r0 top locked
P6 "TBlock_5.08_2" TBLOCK-5.08-2 2100,6325 r0 top
P7 "TBlock_5.08_2" TBLOCK-5.08-2 2700,8100 r0 top locked
P8 "TBlock_5.08_2" TBLOCK-5.08-2 3200,8100 r0 top locked
P9 "09 18 510 7323" 918510x323 400,5650 r0 top locked
P10 "09 18 510 7323" 918510x324 400,6280 r0 top locked
Q1 "PZT2222A" SOT223 4659,2826 r180 top
Q2 "PZT2907A" SOT223 5221,2826 r180 top
Q3 "D45H11" TO-220V 2300,9000 r0 top locked
Q4 "D45H11" TO-220V 1500,9000 r0 top locked
Q5 "D45H11" TO-220V 700,9000 r0 top locked
Q6 "D44H11" TO-220V 3900,9000 r0 top locked
Q7 "D44H11" TO-220V 4700,9000 r0 top locked
Q8 "D44H11" TO-220V 5500,9000 r0 top locked
Q9 "D44H11" TO-220V 3100,9000 r0 top locked
R1 "10" CR2012-0805 5875,569 r90 top
R2 "10" CR2012-0805 3605,542 r270 top
R3 "10" CR2012-0805 523,566 r90 top
R4 "1M" CR2012-0805 4443,3782 r0 top
R5 "1M" CR2012-0805 4736,3999 r0 top
R6 "22.1K" CR2012-0805 4443,3941 r180 top
R6T "120" CR2012-0805 4443,3860 r0 top
R7 "21.0K" CR2012-0805 4770,3807 r90 top
R7T "274" CR2012-0805 4736,3918 r180 top
R8 "10K" CR2012-0805 1142,1347 r0 top
R9 "10K" CR2012-0805 4553,3601 r90 top
R10 "NL" CR2012-0805 697,1489 r270 top
R11 "10" CR2012-0805 4760,3340 r0 top
R12 "NL" CR2012-0805 1105,1214 r270 top
R13 "1M" CR2012-0805 5009,3730 r180 top
R14 "1M" CR2012-0805 5188,3869 r0 top
R15 "0" CR2012-0805 697,1331 r270 top
R16 "32.4K" CR2012-0805 5010,3812 r0 top
R17 "30.9K" CR2012-0805 5189,3789 r180 top
R18 "680" CR2012-0805 4239,2502 r180 top
R19 "100" CR2012-0805 906,922 r90 top
R20 "10K" CR2012-0805 4061,2502 r180 top
R21 "10K" CR2012-0805 5046,3600 r90 top
R22 "100" CR2012-0805 3883,2502 r180 top
R23 "10" CR2012-0805 5320,3420 r270 top
R24 "10K" CR2012-0805 4901,3601 r90 top
R25 "2K" CR2012-0805 4901,3455 r90 top
R26 "2K" CR2012-0805 4900,3300 r90 top
R27 "100" CR2012-0805 4443,2803 r90 top
R28 "100" CR2012-0805 4342,2803 r90 top
R29 "2K" CR2012-0805 4975,3125 r270 top
R30 "1K" CR2012-0805 4304,2925 r180 top
R31 "2K" CR2012-0805 5095,3105 r0 top
R32 "100" CR2012-0805 5318,2353 r180 top
R33 "1K" CR2012-0805 5094,3183 r180 top
R34 "499" CR2012-0805 2866,3633 r180 top
R35 "499" CR2012-0805 725,4478 r180 top
R36 "2K" CR2012-0805 366,4478 r180 top
R37 "2K" CR2012-0805 2581,4281 r270 top
R38 "2K" CR2012-0805 516,5127 r270 top
R39 "2K" CR2012-0805 234,4439 r270 top
R40 "2.21K" CR2012-0805 2715,4281 r270 top
R41 "100" CR2012-0805 2810,4280 r270 top
R42 "1K" CR2012-0805 650,5126 r270 top
R43 "100" CR2012-0805 745,5125 r270 top
R44 "499" CR2012-0805 215,5126 r270 top
R45 "100" CR2012-0805 310,5125 r270 top
R46 "2K" CR2012-0805 852,8378 r180 top
R47 "499" CR2012-0805 3870,3640 r180 top
R48 "499" CR2012-0805 4380,4290 r180 top
R49 "2K" CR2012-0805 4880,4290 r180 top
R50 "2K" CR2012-0805 3610,4280 r270 top
R51 "2K" CR2012-0805 4120,4930 r270 top
R52 "2K" CR2012-0805 4760,4255 r270 top
R53 "100" CR2012-0805 3850,4280 r90 top
R54 "2.21K" CR2012-0805 3745,4280 r90 top
R55 "100" CR2012-0805 4360,4930 r90 top
R56 "1K" CR2012-0805 4255,4930 r90 top
R57 "100" CR2012-0805 4860,4930 r90 top
R58 "499" CR2012-0805 4755,4930 r90 top
R59 "2K" CR2012-0805 5525,8381 r90 top
R60 "499" CR2012-0805 3370,3640 r180 top
R61 "2K" CR2012-0805 3110,4335 r270 top
R62 "100" CR2012-0805 3350,4335 r90 top
R63 "NL" CR2012-0805 3245,4335 r90 top
R64 "Resistor array" RES9-1.27ROW 1200,1580 r0 top
R65 "Resistor array" RES9-1.27ROW 2290,1580 r180 top
R66 "4.99K" CR2012-0805 3650,1275 r180 top
R67 "4.99K" CR2012-0805 3300,1325 r0 top
R68 "4.99K" CR2012-0805 2900,1275 r180 top
R69 "4.99K" CR2012-0805 2550,1325 r0 top
R70 "49.9K" CR2012-0805 3725,1000 r90 top
R71 "100" CR2012-0805 3675,850 r180 top
R72 "100" CR2012-0805 3125,925 r0 top
R73 "49.9K" CR2012-0805 3075,1075 r90 top
R74 "49.9K" CR2012-0805 2975,1000 r90 top
R75 "100" CR2012-0805 2925,850 r180 top
R76 "100" CR2012-0805 2375,925 r0 top
R77 "49.9K" CR2012-0805 2325,1075 r90 top
R78 "4.99K" CR2012-0805 3900,2150 r180 top
R79 "4.99K" CR2012-0805 3550,2200 r0 top
R80 "4.99K" CR2012-0805 3150,2150 r180 top
R81 "4.99K" CR2012-0805 2800,2200 r0 top
R82 "4.99K" CR2012-0805 3975,1875 r90 top
R83 "100" CR2012-0805 3925,1725 r180 top
R84 "100" CR2012-0805 3375,1800 r0 top
R85 "4.99K" CR2012-0805 3325,1950 r90 top
R86 "4.99K" CR2012-0805 3225,1875 r90 top
R87 "100" CR2012-0805 3175,1725 r180 top
R88 "100" CR2012-0805 2625,1800 r0 top
R89 "4.99K" CR2012-0805 2575,1950 r90 top
TP1 "Testpoint" TP1 500,8100 r0 top
TP2 "Testpoint" TP1 4100,8100 r0 top
TP3 "Testpoint" TP1 4400,8100 r0 top
TP4 "Testpoint" TP1 200,1600 r0 top
TP5 "Testpoint" TP1 2000,8100 r0 top
TP6 "Testpoint" TP1 2300,8100 r0 top
TP7 "Testpoint" TP1 6250,5125 r0 top
TP8 "Testpoint" TP1 3800,5625 r90 top
TP9 "Testpoint" TP1 4700,8100 r0 top
TP10 "Testpoint" TP1 1700,8100 r0 top
TP11 "Testpoint" TP1 1400,8100 r90 top
TP12 "Testpoint" TP1 1100,8100 r90 top
TP13 "Testpoint" TP1 800,8100 r90 top
TP14 "Testpoint" TP1 5300,8100 r90 top
TP15 "Testpoint" TP1 5600,8100 r90 top
TP16 "Testpoint" TP1 5900,8100 r90 top
TP17 "Testpoint" TP1 5000,8100 r90 top
U1 "LTC2919" MSOP10 4650,3467 r90 top
U2 "LT1021-10" DIP-8 3925,3095 r180 top
U3 "OP27" SO-G8 931,1266 r180 top
U4 "LTC2919" MSOP10 5151,3467 r90 top
U5 "OP27" SO-G8 4651,2179 r0 top
U6 "OP27" SO-G8 5226,2152 r0 top
U7 "AD829JR" SO-G8 2769,3955 r270 top
U8 "AD829JR" SO-G8 704,4800 r270 top
U9 "AD829JR" SO-G8 269,4800 r270 top
U10 "AD829JR" SO-G8 3780,3955 r270 top
U11 "AD829JR" SO-G8 4290,4605 r270 top
U12 "AD829JR" SO-G8 4790,4605 r270 top
U13 "AD829JR" SO-G8 3280,3955 r270 top
U14 "AD8672" SO-8_N 3400,1075 r180 top
U15 "AD8672" SO-8_N 2650,1075 r180 top
U16 "AD8672" SO-8_N 3650,1950 r180 top
U17 "AD8672" SO-8_N 2900,1950 r180 top
W1 "Jumper" JR2013-0805 3295,4215 r0 top
W2 "Jumper" JR2013-0805 4250,8150 r90 top

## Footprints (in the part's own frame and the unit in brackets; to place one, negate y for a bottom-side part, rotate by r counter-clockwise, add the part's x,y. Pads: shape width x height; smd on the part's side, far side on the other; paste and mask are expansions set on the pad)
918510x323 [mm] "Connector; IDC, Low Profile Male Header, Thru-Hole; 10 Position; Right Angle; Pitch 2.54 mm; Body 20.32 x 8.9 x 9.2 mm (LxWxH)"
  rect 1.65x1.65 hole 1.016: 1(-5.08,-2.54)
  round 1.65 hole 1.016: 2(-5.08,0) 3(-2.54,-2.54) 4(-2.54,0) 5(0,-2.54) 6(0,0) 7(2.54,-2.54) 8(2.54,0) 9(5.08,-2.54) 10(5.08,0)
  silkscreen extent -10.16,0 10.16,9.45
918510x324 [mm] "Connector; IDC, Low Profile Male Header, Thru-Hole; 10 Position; Vertical; Pitch 2.54 mm; Body 20.32 x 9.2 x 9.45 mm (LxWxH)"
  rect 1.65x1.65 hole 1.016: 1(-5.08,-1.27)
  round 1.65 hole 1.016: 2(-5.08,1.27) 3(-2.54,-1.27) 4(-2.54,1.27) 5(0,-1.27) 6(0,1.27) 7(2.54,-1.27) 8(2.54,1.27) 9(5.08,-1.27) 10(5.08,1.27)
  silkscreen extent -10.16,-5.37 10.16,4.6
918550x323 [mm] "Connector; IDC, Low Profile Male Header, Thru-Hole; 50 Position; Right Angle; Pitch 2.54 mm; Body 71.32 x 8.9 x 9.2 mm (LxWxH)"
  rect 1.65x1.65 hole 1.016: 1(-30.48,-2.54)
  round 1.65 hole 1.016: 2(-30.48,0) 3(-27.94,-2.54) 4(-27.94,0) 5(-25.4,-2.54) 6(-25.4,0) 7(-22.86,-2.54) 8(-22.86,0) 9(-20.32,-2.54) 10(-20.32,0) 11(-17.78,-2.54) 12(-17.78,0) 13(-15.24,-2.54) 14(-15.24,0) 15(-12.7,-2.54) 16(-12.7,0) 17(-10.16,-2.54) 18(-10.16,0) 19(-7.62,-2.54) 20(-7.62,0) 21(-5.08,-2.54) 22(-5.08,0) 23(-2.54,-2.54) 24(-2.54,0) 25(0,-2.54) 26(0,0) 27(2.54,-2.54) 28(2.54,0) 29(5.08,-2.54) 30(5.08,0) 31(7.62,-2.54) 32(7.62,0) 33(10.16,-2.54) 34(10.16,0) 35(12.7,-2.54) 36(12.7,0) 37(15.24,-2.54) 38(15.24,0) 39(17.78,-2.54) 40(17.78,0) 41(20.32,-2.54) 42(20.32,0) 43(22.86,-2.54) 44(22.86,0) 45(25.4,-2.54) 46(25.4,0) 47(27.94,-2.54) 48(27.94,0) 49(30.48,-2.54) 50(30.48,0)
  silkscreen extent -35.66,0 35.66,9.45
AC083-033/F [mm] "SMT Electrolyte Capacitor; F Size, Body 8.3 x 8.3 mm (LxW typ)"
  rect 4x2 smd: 1(-3.55,0) 2(3.55,0)
  silkscreen extent -5.2,-4.1 4.1,4.1
AC103-041/G [mm] "SMT Electrolyte Capacitor; G Size, Body 10.3 x 10.3 mm (LxW typ)"
  rect 4.1x2 smd: 1(-4.35,0) 2(4.35,0)
  silkscreen extent -6,-5.1 5.1,5.1
Bracket-RA_708 [mil] "Keystone Electronics right-angle 6-32 steel, 708"
  round 220 hole 125: 1(0,0) 2(0,625)
  silkscreen extent -150,-187 150,813
CA-ALL4 [mil] "Axial film capacitor, Size up to 0.78\"(L) x 0.45\"(D)"
  round 75 hole 40: 1(0,0) 2(600,0) 2(730,0) 2(850,0) 2(980,0)
  silkscreen extent 40,-225 940,225
CA-ALL8 [mil] "Axial film capacitor, Size up to 1.68\"(L) x 0.85\"(D)"
  round 90 hole 50: 1(0,0) 2(1150,0) 2(1370,0) 2(1650,0) 2(1900,0)
  round 75 hole 40: 2(600,0) 2(730,0) 2(850,0) 2(980,0)
  silkscreen extent 50,-425 1850,425
CC2013-0805 [mm] "Chip Capacitor; Body 2.0 x 1.3 mm (LxW typ)"
  rect 1.15x1.4 smd: 1(-0.975,0) 2(0.975,0)
  silkscreen extent -1.85,-0.6 -1.85,0.6
CC3216-1206 [mm] "Chip Capacitor; Body 3.2 x 1.6 mm (LxW typ)"
  rect 1.6x1.8 smd: 1(-1.4,0) 2(1.4,0)
  silkscreen extent -0.3,-0.8 0.3,0.8
CR2012-0805 [mm] "Chip Resistor; Body 2.0 x 1.3 mm (LxW typ)"
  rect 1.3x1.5 smd: 1(-0.95,0) 2(0.95,0)
DB9F-RA [mm] "Receptiacle; D Subminiature 9 Position; Right Angle"
  rect 1.69x1.69 hole 1.016: 1(-5.54,-1.42)
  round 1.69 hole 1.016: 2(-2.77,-1.42) 3(0,-1.42) 4(2.77,-1.42) 5(5.54,-1.42) 6(-4.155,1.42) 7(-1.385,1.42) 8(1.385,1.42) 9(4.155,1.42)
  round 4.76 hole 3.175: 10(-12.495,0) 11(12.495,0)
  silkscreen extent -15.4,-2.9 15.4,6.5
DB25F-RA [mm] "Receptiacle; D Subminiature 25 Position; Right Angle"
  rect 1.69x1.69 hole 1.016: 1(-16.566,-1.42)
  round 1.69 hole 1.016: 2(-13.805,-1.42) 3(-11.044,-1.42) 4(-8.283,-1.42) 5(-5.522,-1.42) 6(-2.761,-1.42) 7(0,-1.42) 8(2.761,-1.42) 9(5.522,-1.42) 10(8.283,-1.42) 11(11.044,-1.42) 12(13.805,-1.42) 13(16.566,-1.42) 14(-15.185,1.42) 15(-12.424,1.42) 16(-9.663,1.42) 17(-6.902,1.42) 18(-4.142,1.42) 19(-1.381,1.42) 20(1.381,1.42) 21(4.142,1.42) 22(6.903,1.42) 23(9.664,1.42) 24(12.425,1.42) 25(15.186,1.42)
  round 4.76 hole 3.175: 26(-23.526,0) 27(23.526,0)
  silkscreen extent -26.5,-3 26.6,6.5
DIP-8 [mm] "DIP; 8 Leads; Row Spacing 7.62 mm; Pitch 2.54 mm"
  rect 1.5x1.5 hole 0.889: 1(-3.81,-3.81)
  round 1.5 hole 0.889: 2(-1.27,-3.81) 3(1.27,-3.81) 4(3.81,-3.81) 5(3.81,3.81) 6(1.27,3.81) 7(-1.27,3.81) 8(-3.81,3.81)
  silkscreen extent -5.15,-2.65 5.15,2.65
DO-SMA [mm] "DO-214-AC/SMA; 2 C-Bend Leads; Body 5 x 2.7 mm, inc. leads (LxW)"
  rect 2.4x1.8 smd: 1(-2.05,0) 2(2.05,0)
  silkscreen extent -3.65,-1.3 3.95,1.3
DO-SOD123 [mm] "SOD-123; 2 Leads; Body 2.7 x 1.6 mm, (LxW)"
  rect 1.6x0.8 smd: 1(-1.7,0) 2(1.7,0)
  silkscreen extent -1.45,-0.85 1.45,0.85
DSUB-PWR5-RAPLUG [mil] "Right angle 5 pin power D sub Plug"
  round 200 hole 102.36: 1(0,-570) 2(0,-302) 3(0,-34) 4(0,234) 5(0,570)
  round 190 hole 125: 6(0,-925.98) 7(0,926)
  silkscreen extent -115,-1050 255,1050
JR2013-0805 [mm] "Jumper; 805 size"
  rect 0.9x1.4 smd paste-10 mask+0.1: 1(-1.05,0) 2(1.05,0)
  rect 0x0 smd paste-10 mask+0.8: 1(0,0)
  Top Layer region: -0.2,0.7 0.6,0 -0.2,-0.7 1.5,-0.7 1.5,0.7
  Top Layer region: -1.5,0.7 -0.6,0.7 0.2,0 -0.6,-0.7 -1.5,-0.7
LIGO_LOGO [mil] "LIGO logo"
  silkscreen extent 3,-402 511,-3
MSOP10 [mm]
  rect 1x0.297 smd: 1(0,0) 2(0,-0.5) 3(0,-1) 4(0,-1.5) 5(0,-2) 6(4.3,-2) 7(4.3,-1.5) 8(4.3,-1) 9(4.3,-0.5) 10(4.3,0)
  silkscreen extent 1.33,-2.25 2.97,0.25
RELAY_IMG [mm] "IM series relay, gull-wing SMD"
  rect 2.5x0.7 smd: 1(5.54,-2.2) 2(5.54,-4.4) 3(5.54,0) 4(-0.46,-2.2) 5(-0.46,-4.4) 6(-0.46,0) 7(5.54,-7.6) 8(-0.46,-7.6)
  silkscreen extent -0.51,-8.89 5.59,1.27
RES9-1.27ROW [mil] "Resistor chip array, 1.27mm spacing, single row, 9 pads"
  rect 30x125 smd: 1(0,0) 2(50,0) 3(100,0) 4(150,0) 5(200,0) 6(250,0) 7(300,0) 8(350,0) 9(400,0)
  silkscreen extent -65,-90 465,60
SO-8_N [mm] "SOIC, 8-Leads, Body 4.9x3.9mm, Pitch 1.27mm, IPC Medium Density"
  oval 2.2x0.6 smd: 1(-2.4,1.905) 2(-2.4,0.635) 3(-2.4,-0.635) 4(-2.4,-1.905) 5(2.4,-1.905) 6(2.4,-0.635) 7(2.4,0.635) 8(2.4,1.905)
  silkscreen extent -2.53,-2.5 0.9,2.88, body extent -1.95,-2.45 1.95,2.45, height 1.75
SO-G3/C2.25 [mm] "SOT-23; 3 Leads; Body 3.0 x 2.5 mm, inc. leads (LxW max)"
  rect 0.95x1 smd: 1(-0.95,-1.125) 2(0.95,-1.125) 3(0,1.125)
  silkscreen extent -2.1,-1.25 1.32,1.13
SO-G8 [mm] "Small Outline; 8 Leads; Body Width 3.9 mm; Pitch 1.27 mm"
  rect 0.6x2.2 smd: 1(-1.905,-2.6) 2(-0.635,-2.6) 3(0.635,-2.6) 4(1.905,-2.6) 5(1.905,2.6) 6(0.635,2.6) 7(-0.635,2.6) 8(-1.905,2.6)
  silkscreen extent -2.88,-2.72 2.5,1.1
SOT223 [mm] "SOT-223/SC-73; 4 Leads; Body 6.7 x 7.3 mm, inc. leads (LxW max)"
  rect 1.1x2.15 smd: 1(-2.3,-3.1) 2(0,-3.1) 3(2.3,-3.1)
  rect 3.5x2.15 smd: 4(0,3.1)
  silkscreen extent -3.35,-4.85 3.35,1.63
TBLOCK-5.08-2 [mil] "Terminal Block, 5.08mm, 2pin"
  rect 100x100 hole 65: 1(-100,0)
  round 100 hole 65: 2(100,0)
  silkscreen extent -200,-160 200,160
TBLOCK-5.08-12 [mil] "Terminal Block, 5.08mm, 12pin"
  rect 100x100 hole 65: 1(-1100,0)
  round 100 hole 65: 2(-900,0) 3(-700,0) 4(-500,0) 5(-300,0) 6(-100,0) 7(100,0) 8(300,0) 9(500,0) 10(700,0) 11(900,0) 12(1100,0)
  silkscreen extent -1200,-160 1200,160
TO-220V [mil]
  rect 70x70 hole 40: 1(0,0) 2(100,0) 3(200,0)
  silkscreen extent -60,-60 260,100
TP1 [mil] "Testpoint pin"
  round 100 hole 65: 1(0,0)

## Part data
B1 B2 B3 B4: library part Bracket_708, "Keystone Electronics right-angle 6-32 steel, 708"
C1 C2 C3 C4 C5 C6 C11 C12 C14 C15 C16 C17 C19 C20 C21 C22 C23 C24 C25 C26 C27 C28 C29 C30 C31 C32 C33 C34 C35 C36 C37 C38 C39 C40 C41 C42 C43 C44 C45 C46 C47 C48 C49 C50 C51 C52 C53 C54 C55 C56 C57 C58 C59 C62 C63 C64 C65 C68 C69 C70 C71 C75 C76 C77 C78 C79 C80 C81 C82 C83 C84 C85 C86 C87 C88 C89 C90: library part ChipCap, "Capacitor, surface mount"
C7 C8 C9 C10 C60 C61 C66 C67 C72 C73 C74: library part ChipElectrolyte, "Electrolyte capacitor, surface mount"
C13 C18: library part CapFilmAxial, "Film Capacitor, axial lead"
D1 D2 D3 D4 D5 D6 D11 D13 D16 D17 D21 D22 D23 D24 D25 D26 D30 D31 D32 D33 D34 D35 D37 D38: library part DIODE_SHOTTKY, "Single shottky diode"
D7 D8 D10 D12 D14 D15 D18 D19 D20 D27 D28 D29 D36: library part DIODE_SOT23, "Single diode in SOT23 package"
D9: library part DIODE_ZENER, "Single zener diode"
FR1 FR2 FR3 FR4 FR5 FR6 FR7 FR8 FR9 FR10 FR11 FR12 FR13 FR14 FR15 FR16 FR17: library part BLM31PG121SN1, "ferrite bead, 120Ohm at 100MHz, 1206"
J1: "Receptacle Assembly, 9 Position, Right Angle, .318 Series"
J2: "Receptacle Assembly, 25 Position, Right Angle, .318 Series"
K1 K2: library part Relay_DPDT, "Dual-pole dual-throw relay"
LOGO1: library part LIGO_logo
P1: library part DSUB_PWR_5PIN, "5 contact Dsub Power Connector"
P2: "Flat Cable Connector (IDC), PCB Transition Connector, 2 Rows, Kinked Solder Pin, 50 Contacts"
P3 P4: "Terminal block, 5.08mm, 12-Pin"
P5 P6 P7 P8: "Terminal block, 5.08mm, 2-Pin"
P9 P10: "Flat Cable Connector (IDC), Low-Profile Male Header, Angled Solder Pin, 10 Contacts, Performance Level 3"
Q1: library part PZTA42, "NPN General Purpose Transistor"
Q2: library part BCP51, "PNP Medium Power Transistor"
Q3 Q4 Q5: library part D45H8, "PNP Power Amplifier"
Q6 Q7 Q8 Q9: library part D44H8, "NPN Power Amplifier"
R1 R2 R3 R4 R5 R6 R6T R7 R7T R8 R9 R10 R11 R12 R13 R14 R15 R16 R17 R18 R19 R20 R21 R22 R23 R24 R25 R26 R27 R28 R29 R30 R31 R32 R33 R34 R35 R36 R37 R38 R39 R40 R41 R42 R43 R44 R45 R46 R47 R48 R49 R50 R51 R52 R53 R54 R55 R56 R57 R58 R59 R60 R61 R62 R63 R66 R67 R68 R69 R70 R71 R72 R73 R74 R75 R76 R77 R78 R79 R80 R81 R82 R83 R84 R85 R86 R87 R88 R89: library part ChipRes1, "Resistor, surface mount"
R64 R65: library part RES8_BUSROW, "Resistor Network, bussed row, 8 resistors"
TP1 TP4 TP7: library part TP_GND, "Testpoint, black"
TP2 TP3 TP14 TP15 TP16 TP17: library part TP_POSITIVE, "Testpoint, red"
TP5 TP6 TP11 TP12 TP13: library part TP_NEGATIVE, "Testpoint, white"
TP8 TP9 TP10: library part TP_SIGNAL, "Testpoint, yellow"
U1 U4: "Precision Triple/Dual Input UV, OV and Negative Voltage Monitor"
U2: library part LT1021-7, "Voltage Ref"
U3 U5 U6: library part OP27GS, "Low-Noise, Precision Operational Amplifier"
U7 U8 U9 U10 U11 U12 U13: "High-Speed, Low-Noise Video Operational Amplifier"
U14 U15 U16 U17: library part OP285ES, "Dual, 9MHz Precision Operational Amplifier"
W1 W2: "Jumper Pad"

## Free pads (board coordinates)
  round 250 hole 150: 0(1050,4500) 0(3200,6400) 0(5250,4500)
  round 220 hole 125: 1(2300,5200)

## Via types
v1: diameter 35, hole 15, Top Layer to Bottom Layer, 147 vias
v2: diameter 50, hole 25, Top Layer to Bottom Layer, 19 vias
v3: diameter 280/400 (per signal layer), hole 150, Top Layer to Bottom Layer, 8 vias

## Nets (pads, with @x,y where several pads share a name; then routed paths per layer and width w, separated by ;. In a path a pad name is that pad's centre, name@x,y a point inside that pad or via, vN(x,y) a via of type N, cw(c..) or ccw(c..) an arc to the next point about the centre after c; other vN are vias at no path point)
+5: C58.2 C61.1 D30.2 P4.12 Q8.3 R59.1 TP16.1 | length 1577.9
  Top Layer w25: R59.1@5525,8343.6 5698.6,8343.6 5700,8345 ; Q8.3@5700,9000 5700,8950 5750,8900 ; TP16.1@5900,8100 5800,8200 ; C58.2@5911.61,8300 5900,8300 5800,8200 ; D30.2@5975,8900 5750,8900 ; 5700,8345 5700,8300 5800,8200 ; 5700,8345 5700,8620 5750,8670 5750,8900
+5C: P10.10 Q8.1 | length 6112.6
  Top Layer w15: P10.10@600,6330 605,6325 v1(1200,6325)
  Bottom Layer w15: v1(1200,6325) 2750,7875 2825,7875 2975,8025 2975,8150 3175,8350 4425,8350 4625,8550 5100,8550 5500,8950 Q8.1@5500,9000
+15: C65.2 C67.1 D35.2 P4.4 P6.1 P7.1 P8.1 Q7.3 TP15.1 | length 1606.4
  Top Layer w25: Q7.3@4900,9000 4900,8954 4977,8877 ; C65.2@4977,8556.39 4977,8745 ; D35.2@5079.29,8900 5000,8900 4977,8877 ; TP15.1@5600,8100 5320,8380 5320,8600 5177.24,8742.76 4979.24,8742.76 4977,8745 ; 4977,8745 4977,8877
+15C: P10.9 Q7.1 | length 5335.2
  Bottom Layer w15: P10.9@600,6230 1030,6230 2725,7925 2800,7925 2900,8025 2900,8175 3150,8425 4075,8425 4650,9000 Q7.1@4700,9000
+18: C54.1 C55.1 D32.1 D33.1 P4.7 TP3.1 | length 350.1
  Top Layer w25: D32.1@4679.39,8759.91 C54.1@4679.39,8638 4682.39,8635 v2(4750,8635) ; D33.1@5479.29,8760 v2(5479.29,8671.09) C55.1@5527,8623.39
+21: C69.2 C73.1 D34.2 P4.2 Q6.3 TP14.1 | length 4338.9
  Top Layer w25: Q6.3@4100,9000 4100,8950 4172,8878 4172,8750 ; C69.2@4172,8562.39 4172,8750 ; 4172,8872 4200,8900 D34.2@4279.29,8900 ; TP14.1@5300,8100 5095,8305 4755,8305 4397,8663 4397,8747.76 4174.24,8747.76 4172,8750
  Bottom Layer w50: P4.2@4200,6250 4200,6520 5300,7620 TP14.1@5300,8100
+21C: P10.7 Q6.1 | length 4898.8
  Bottom Layer w15: P10.7@500,6230 505,6230 550,6275 550,6400 575,6425 1125,6425 2700,8000 2700,8425 3100,8825 3775,8825 3900,8950 Q6.1@3900,9000
+24: C53.1 C71.1 D31.1 D37.1 P4.6 TP2.1 W2.1 | length 616.8
  Top Layer w8: W2.1@4250,8108.66 W2.1@4250,8150
  Top Layer w25: D37.1@3100.39,8758.91 C71.1@3100.39,8638 3138.39,8600 v2(3200,8600) ; D31.1@3899.29,8760 3900.39,8758.91 C53.1@3900.39,8633 3900,8632.61 v2(3900,8575)
  Top Layer w50: TP2.1@4100,8100 4241.34,8100 W2.1@4250,8108.66
+24A: P10.8 Q9.1 | length 3937.3
  Bottom Layer w15: P10.8@500,6330 500,6400 575,6475 875,6475 2425,8025 2425,8350 3075,9000 Q9.1@3100,9000
+24AMP: C70.2 C74.1 D38.2 P4.5 P5.1 Q9.3 TP17.1 W2.2 | length 3002.2
  Top Layer w25: Q9.3@3300,9000 3300,8950 3374,8876 ; D38.2@3479.29,8900 3398,8900 3374,8876 ; 3600,8202.82 3422.18,8202.82 3300,8325 3300,8525 3326.39,8551.39 C70.2@3374,8551.39 3374,8743.53 ; C74.1@3600,8741.76 3375.76,8741.76 3374,8743.53 ; 3374,8743.53 3374,8876
  Top Layer w50: P5.1@3600,8100 3600,8202.82 4897.18,8202.82 TP17.1@5000,8100
+VREF: P10.4 TP9.1 | length 5133.2
  Top Layer w15: P10.4@300,6330 395,6425 v1(1425,6425)
  Bottom Layer w15: v1(1425,6425) 2075,6425 3525,7875 4475,7875 TP9.1@4700,8100
-5: C57.1 C60.2 D21.1 P4.11 Q5.3 R46.2 TP13.1 | length 1384.6
  Top Layer w25: TP13.1@800,8100 800,8465 891.39,8556.39 C57.1@979,8556.39 979,8740 ; Q5.3@900,9000 900,8950 979,8871 ; D21.1@1069.29,8900 1008,8900 979,8871 ; C60.2@1203,8739.76 979.24,8739.76 979,8740 ; 979,8740 979,8871
-5C: P10.1 Q5.1 | length 3018.5
  Bottom Layer w15: P10.1@200,6230 150,6280 150,7675 300,7825 300,8550 700,8950 Q5.1@700,9000
-15: C64.1 C66.2 D26.1 P4.3 Q4.3 TP12.1 | length 1676.1
  Top Layer w25: TP12.1@1100,8100 1539.39,8539.39 C64.1@1781,8539.39 1781,8869 ; Q4.3@1700,9000 1700,8950 1781,8869 ; 1782.24,8723.76 C66.2@2000,8723.76 ; D26.1@1869.29,8900 1812,8900 1781,8869
-15C: P10.3 Q4.1 | length 3674.6
  Bottom Layer w15: P10.3@300,6230 250,6280 250,7710 350,7810 350,8425 775,8850 1400,8850 1500,8950 Q4.1@1500,9000
-18: C39.1 C40.1 D23.2 D24.2 P4.9 TP5.1 | length 425.4
  Top Layer w25: D24.2@644.29,8675 644.29,8565.09 C40.1@650.39,8559 659.39,8550 v1(725,8550) ; v1(1455,8540) 1465,8540 1500.39,8575.39 C39.1@1500.39,8645 ; C39.1@1494.29,8651.09 D23.2@1494.29,8750
-21: C68.1 C72.2 D25.1 P4.1 Q3.3 TP11.1 | length 5322.7
  Top Layer w25: TP11.1@1400,8100 1610,8310 2165,8310 2405.39,8550.39 C68.1@2575,8550.39 2577.24,8552.62 2577.24,8737.76 ; Q3.3@2500,9000 2500,8950 2577.24,8872.76 ; D25.1@2679.29,8900 2604.47,8900 2577.24,8872.76 ; C72.2@2800,8737.76 2577.24,8737.76 ; 2577.24,8737.76 2577.24,8872.76
  Top Layer w50: C72.2@2800,8719.76 2975,8544.76 2975,7925 3275,7625 3275,6675 3700,6250 P4.1@4000,6250
-21C: P10.5 Q3.1 | length 4067.1
  Bottom Layer w15: P10.5@400,6230 350,6280 350,7100 500,7250 1300,7250 2250,8200 2250,8900 2300,8950 Q3.1@2300,9000
-24: C38.1 D22.2 P4.10 TP6.1 | length 217.7
  Top Layer w25: D22.2@2289.29,8750 2309.39,8729.91 C38.1@2309.39,8643 2309.39,8555.61 v2(2310,8555)
  Bottom Layer w50: TP6.1@2300,8100 TP6.1@2310,8110
-VREF: P10.2 TP10.1 | length 2757.4
  Top Layer w12: P10.2@200,6330 200,7225 v1(300,7325)
  Bottom Layer w12: v1(300,7325) 925,7325 TP10.1@1700,8100
BIAS1: J2.10 P2.43 | length 6382.3
  Top Layer w12: v1(2300,1800) 2300,4220 ; 2300,4210 2300,4300 3200,5200 P2.43@3200,5550
  Bottom Layer w12: J2.10@1123.9,315.91 1123.9,923.9 1775,1575 2250,1575 2300,1625 v1(2300,1800)
BIAS2: J2.11 P2.39 R80.2 R81.2 U17.3 | length 7578
  Top Layer w12: v1(2200,1775) v1(2200,2200) 2200,4350 3000,5150 P2.39@3000,5550 ; R81.2@2837.4,2200 v1(2900,2200) 3062.6,2200 R80.2@3112.6,2150 3112.6,2002.6 3085,1975 U17.3@2994.49,1975
  Bottom Layer w12: J2.11@1015.2,315.91 1015.2,890.2 1750,1625 2175,1625 2200,1650 v1(2200,1775) ; v1(2200,2200) v1(2900,2200)
BIAS2_P: J1.4 R86.1 R87.1 | length 1613.8
  Top Layer w12: v1(3075,1625) 3114.89,1625 3212.4,1722.51 R87.1@3212.4,1725 3225,1737.6 R86.1@3225,1837.6
  Bottom Layer w12: v1(3075,1625) 3090.94,1609.06 J1.4@3090.94,315.91
BISA2_N: J1.9 R88.1 R89.1 | length 2018.8
  Top Layer w12: R89.1@2575,1912.6 2575,1812.6 R88.1@2587.6,1800 2587.6,1797.51 2760.11,1625 v1(2950,1625)
  Bottom Layer w12: v1(2950,1625) 3042,1533 3042,204.09 J1.9@3036.42,204.09
CTRL: P2.49 R8.2 R78.2 R79.2 U16.3 | length 8158.7
  Top Layer w12: R8.2@1179.4,1347 1179.4,910.6 v1(1180,910) ; v1(2400,1800) v1(2400,2275) 2400,4260 3500,5360 P2.49@3500,5550 ; R79.2@3587.4,2200 v1(3650,2200) 3812.6,2200 R78.2@3862.6,2150 3862.6,2002.6 3835,1975 U16.3@3744.49,1975
  Bottom Layer w12: v1(1180,910) 1720,1450 2175,1450 2400,1675 v1(2400,1800) ; v1(2400,2275) 3575,2275 v1(3650,2200)
CTRL_N: J1.7 R84.1 R85.1 | length 1759.3
  Top Layer w12: v1(3250,1625) 3325,1700 3325,1800 R84.1@3337.6,1800 3325,1812.6 R85.1@3325,1912.6
  Bottom Layer w12: v1(3250,1625) 3250,700 3254.53,695.47 J1.7@3254.53,204.09
CTRL_P: J1.2 R82.1 R83.1 | length 2152.7
  Top Layer w12: v1(3325,1625) 3864.89,1625 R83.1@3962.4,1722.51 ; R83.1@3962.4,1725 3975,1737.6 R82.1@3975,1837.6
  Bottom Layer w12: J1.2@3309.06,315.91 3375,381.85 3375,1575 v1(3325,1625)
ERR: P2.47
EXC_EN: FR6.1 P2.32 | length 5066.3
  Top Layer w12: FR6.1@1831,942.12 1831,4371 2648.16,5188.16 2648.16,5601.84 P2.32@2600,5650
EXC_SW: FR4.1 P2.34 R65.8 | length 5063.4
  Top Layer w12: FR4.1@1938,942.12 1938,4358 2748.16,5168.16 2748.16,5601.84 P2.34@2700,5650
GAIN0: P2.23
GAIN1: P2.25
GAIN2: P2.27
GAIN3: P2.29
GND: B2.1 B2.2 B4.1 B4.2 C1.2 C2.1 C3.1 C4.2 C5.2 C6.1 C7.2 C8.2 C9.1 C10.1 C11.2 C12.1 C13.2 C14.1 C15.1 C16.1 C17.1 C18.2 C19.1 C21.2 C22.2 C23.1 C25.2 C26.1 C27.1 C28.1 C29.1 C30.1 C31.1 C32.1 C33.1 C34.1 C41.2 C42.2 C43.2 C44.2 C45.2 C46.2 C47.2 C48.2 C49.2 C56.2 C59.2 C62.2 C75.2 C76.2 C77.2 C78.2 C83.2 C84.2 C85.2 C86.2 D5.1 D6.2 D9.1 D12.1 D13.1 D14.3 D16.2 J2.13 J2.22 J2.23 J2.24 J2.25 K1.8 K2.7 P1.3 P2.2 P2.4 P2.6 P2.8 P2.14 P2.38 P2.40 P2.42 P2.44 P2.46 P2.48 P2.50 P3.8 P9.6 pad.0@1050,4500 pad.0@5250,4500 pad.1 R1.2 R2.1 R3.2 R6.1 R10.1 R12.2 R16.1 R26.1 R30.2 R33.2 R37.1 R38.1 R39.2 R50.1 R51.1 R52.2 R61.1 TP4.1 TP7.1 U1.6 U1.8 U2.4 U4.6 U4.8 U5.4 U6.3 U7.7 U8.7 U9.7 U10.4 U11.4 U12.4 U13.4 U14.5 U15.5 U16.5 U17.5 | length 7867.5
  Top Layer w10: R6.1@4480.4,3941 v1(4480.4,3993.4) ; U1.8@4689.37,3636.29 v1(4689.37,3719.37) ; U1.6@4728.74,3636.29 v1(4780,3636.29) ; U4.8@5190.37,3636.29 v1(5190.37,3714.63) ; U4.6@5229.74,3636.29 v1(5293.71,3636.29)
  Top Layer w12: R3.2@523,603.4 v1(676.6,603.4) ; R10.1@697,1526.4 v1(697,1587) ; v1(783,1237) C16.1@783,1290.61 ; C15.1@1034.39,1065 v1@1084.39,1115 ; v1(1085,1115) v1@1084.39,1115 ; R12.2@1105,1176.6 1105,1135.61 v1@1084.39,1115 ; U15.5@2555.51,1150 2555.51,1205.51 v1(2575,1225) 2600,1250 C77.2@2686.61,1250 ; C78.2@2613.39,900 v1(2675,900) ; U17.5@2805.51,2025 2805.51,2080.51 v1(2825,2100) 2850,2125 C85.2@2936.61,2125 ; C86.2@2863.39,1775 v1(2925,1775) ; U14.5@3305.51,1150 3305.51,1205.51 v1(3325,1225) 3350,1250 C75.2@3436.61,1250 ; C76.2@3363.39,900 v1(3425,900) ; v1(3530.61,579.39) C6.1@3693,579.39 ; U16.5@3555.51,2025 3555.51,2080.51 v1(3575,2100) 3600,2125 C83.2@3686.61,2125 ; C84.2@3613.39,1775 v1(3675,1775) ; U2.4@3775,3245 3775,3304.39 C14.1@3828.61,3358 ; D13.1@4259.29,3040 D13.1@4266.6,3032.69 ; v1(4553,3368) C12.1@4553,3411.61 ; C19.1@4703.39,2399 v1(4761,2399) ; v1(4726,1996) U5.4@4726,2076.64 ; C21.2@4861,2606.61 4867.61,2600 v1(4920,2600) ; D12.1@4902.71,2088.4 v1(4902.71,2152.29) D14.3@4902.71,2241 ; R16.1@4972.6,3812 v1(4972.6,3862.6) ; C25.2@5032,2781.39 v1(5032,2828) ; v1(5045,3375) C17.1@5045,3418.61 ; R33.2@5056.6,3183 v1@5056.6,3243.4 ; v1(5095,2275) 5115.61,2295.61 C22.2@5115.61,2353 ; U6.3@5251,2049.64 5251,1975 5270,1956 C23.1@5327.61,1956 ; v1(5293.71,3636.29) 5310.64,3636.29 D9.1@5420,3526.93 ; R1.2@5875,606.4 v1(6028.6,606.4)
  Top Layer w15: C28.1@152,4401.61 v1(286.61,4401.61) ; C31.1@235.39,4637 v1(283,4637) C34.1@328.61,4637 ; v1(270,4825) U9.7@371.36,4825 420,4825 ; R38.1@516,5164.4 v1(516,5211) ; C27.1@587,4401.61 v1(721.61,4401.61) ; C30.1@670.39,4637 v1(718,4637) C33.1@763.61,4637 ; v1(705,4825) U8.7@806.36,4825 855,4825 ; R37.1@2581,4318.4 v1(2581,4366) ; C26.1@2652,3556.61 v1(2786.61,3556.61) ; C29.1@2735.39,3792 v1(2783,3792) C32.1@2828.61,3792 ; v1(2770,3980) U7.7@2871.36,3980 2920,3980 ; R61.1@3110,4372.4 v1(3110,4420) ; v1(3133.39,3566.61) C56.2@3180,3566.61 ; U13.4@3177.64,3880 3191.61,3866.02 C59.2@3191.61,3790 ; C62.2@3433.39,3795 v1(3480,3795) ; R50.1@3610,4317.4 v1(3610,4365) ; v1(3633.39,3566.61) C41.2@3680,3566.61 ; U10.4@3677.64,3880 3691.61,3866.02 C44.2@3691.61,3790 ; C47.2@3933.39,3795 v1(3980,3795) ; R51.1@4120,4967.4 v1(4120,5015) ; v1(4143.39,4216.61) C42.2@4190,4216.61 ; U11.4@4187.64,4530 4201.61,4516.02 C45.2@4201.61,4440 ; v1(4205,2925) R30.2@4266.6,2925 D13.1@4266.6,3032.69 ; C48.2@4443.39,4445 v1(4490,4445) ; v1(4633.39,4216.61) C43.2@4680,4216.61 R52.2@4759.02,4216.61 ; U12.4@4687.64,4530 4701.61,4516.02 C46.2@4701.61,4440 ; R26.1@4900,3262.6 4912.6,3250 v1@5055,3250 ; C49.2@4943.39,4445 v1(4990,4445)
  Top Layer w25: C7.2@4050.26,1073 C8.2@4470.74,1073 ; D5.1@4240,1700.71 4379.29,1840 v1(4420,1840) ; K1.8@4420.79,1738.11 v1@4420.79,1840 ; C2.1@4485.39,539 C3.1@4600.61,539 ; v2(4965,975) 4965,1015.26 C9.1@5019.74,1070 ; C4.2@5296.39,540 C5.2@5412.61,540 ; v1(5440,3160) D16.2@5559.29,3160 ; v1(5478.43,1840) v1@5479.21,1840 ; K2.7@5479.21,1738.11 v1@5479.21,1840 ; D6.2@5660,1700.71 5520.71,1840 v1@5479.21,1840 ; C10.1@5800,1141.26 6173.74,1141.26 B4.2@6250,1065
  other v1: 5255,1965 5055,3245 3191.61,3845 3691.61,3845 4201.61,4495 4701.61,4495
  other v2: 4540,539 5350,540 4300,1073
INTEXT: FR8.1 P2.30 | length 5141.9
  Top Layer w12: FR8.1@1721,942.12 1721,4961 2220,5460 2410,5460 2450,5500 2450,5600 P2.30@2500,5650
LOOP: P2.26
MON1: P2.45 R66.2 R67.2 U14.3 | length 5951.8
  Top Layer w12: P2.45@3300,5550 3300,5240 2350,4290 2350,1775 2675,1450 3275,1450 3337.4,1387.6 R67.2@3337.4,1325 3562.6,1325 R66.2@3612.6,1275 3612.6,1127.6 3585,1100 U14.3@3494.49,1100
MON1_N: J1.6 R72.1 R73.1 | length 953
  Top Layer w12: R73.1@3075,1037.6 3075,937.6 R72.1@3087.6,925 3087.6,862.4 3363.58,586.42 J1.6@3363.58,204.09
MON1_P: J1.1 R70.1 R71.1 | length 847
  Top Layer w12: J1.1@3418.11,315.91 3418.11,593.11 3525,700 3650,700 3712.4,762.4 R71.1@3712.4,850 3725,862.6 R70.1@3725,962.6
MON2: P2.41 R68.2 R69.2 U15.3 | length 5289.7
  Top Layer w12: U15.3@2744.49,1100 2835,1100 2862.6,1127.6 R68.2@2862.6,1275 2812.6,1325 R69.2@2587.4,1325 2587.4,1437.6 2250,1775 2250,4320 3100,5170 P2.41@3100,5550
MON2_N: J1.8 R76.1 R77.1 | length 1495.5
  Top Layer w12: R77.1@2325,1037.6 2325,937.6 R76.1@2337.6,925 2337.6,862.4 2450,750 3000,750 3145.47,604.53 J1.8@3145.47,204.09
MON2_P: J1.3 R74.1 R75.1 | length 750.3
  Top Layer w12: R74.1@2975,962.6 2975,862.6 R75.1@2962.4,850 3200,612.4 J1.3@3200,315.91
N5: D20.3 P2.11 P3.11 R44.1 | length 7336.4
  Top Layer w15: R44.1@217.71,5166.11 D20.3@217.71,5299 217.71,5392.71 275,5450 900,5450
  Top Layer w50: P2.11@1600,5550 1600,5460 1490,5350 1000,5350 900,5450 900,5775 1035.32,5910.32 5889.68,5910.32 P3.11@6000,5800
N5C: D20.1 P9.1 R45.1 | length 479.5
  Top Layer w15: R45.1@306.29,5166.11 v1(306.29,5210) D20.1@306.29,5261.6
  Bottom Layer w15: P9.1@200,5550 200,5450 306.29,5343.71 v1(306.29,5210)
N15: C16.2 C75.1 C77.1 C83.1 C85.1 D19.3 P2.7 P3.3 R42.1 U3.4 U14.4 U15.4 U16.4 U17.4 | length 991.5
  Top Layer w12: C16.2@783,1367.39 783,1413 v1(800,1430) 845,1430 856,1419 U3.4@856,1368.36
  Top Layer w15: R42.1@652.71,5166.11 D19.3@652.71,5299 ; U15.4@2744.49,1150 2763.39,1168.9 2763.39,1200 ; C77.1@2763.39,1250 2763.39,1200 ; v1(2825,1200) 2763.39,1200 ; U17.4@2994.49,2025 3013.39,2043.9 3013.39,2075 ; C85.1@3013.39,2125 3013.39,2075 ; v1(3075,2075) 3013.39,2075 ; U14.4@3494.49,1150 3513.39,1168.9 3513.39,1200 ; C75.1@3513.39,1250 3513.39,1200 ; v1(3575,1200) 3513.39,1200 ; U16.4@3744.49,2025 3763.39,2043.9 3763.39,2075 ; C83.1@3763.39,2125 3763.39,2075 ; v1(3825,2075) 3763.39,2075
  other v1: 652.71,5210
N15C: D19.1 P9.3 R43.1 | length 764.7
  Top Layer w15: R43.1@741.29,5166.11 v1(741.29,5210) D19.1@741.29,5261.6
  Bottom Layer w15: P9.3@300,5550 300,5450 425,5325 675,5325 741.29,5258.71 v1(741.29,5210)
N18: C25.1 D17.2 K2.6 P3.9 R14.2 | length 367
  Top Layer w12: C25.1@5032,2704.61 5032.66,2703.95 v1(5100,2703.95)
  Top Layer w15: R14.2@5225.4,3869 5226.98,3870.57 v1(5226.98,3921.98)
  Top Layer w25: D17.2@5100,2560.71 v1(5100,2703.95) ; v1@5180,1400 K2.6@5180,1501.89
  other v1: 5180.79,1400
N21: D18.3 P2.3 P3.1 R40.1 | length 6590.8
  Top Layer w15: R40.1@2717.71,4321.11 D18.3@2717.71,4454 2717.71,4507.71 3685,5475 v1(3850,5475)
  Bottom Layer w15: v1(3850,5475) 4075,5475 4300,5700 4300,5850 4250,5900 4100,5900 P3.1@4000,5800
  Bottom Layer w50: P2.3@1200,5550 1200,5500 1150,5450 1025,5450 910,5565 910,5785 1035.32,5910.32 3889.68,5910.32 P3.1@4000,5800
N21C: D18.1 P9.5 R41.1 | length 3067.5
  Top Layer w15: R41.1@2806.29,4321.11 v1(2806.29,4365) D18.1@2806.29,4416.6
  Bottom Layer w15: P9.5@400,5550 400,5500 525,5375 785,5375 1795,4365 2445,4365 2500,4310 2640,4310 2695,4365 v1(2806.29,4365)
N24: C5.1 C10.2 C23.2 C29.2 C30.2 C31.2 D2.1 D4.1 D6.1 K2.8 P1.5 P3.10 R5.2 U6.4 U7.4 U8.4 U9.4 | length 8000.1
  Top Layer w12: U6.4@5301,2049.64 5370.36,2049.64 v1(5404.39,2015.61) C23.2@5404.39,1956 C23.2@5408.39,1960
  Top Layer w15: C31.2@158.61,4637 158.61,4678.61 166.64,4686.64 U9.4@166.64,4725 ; C30.2@593.61,4637 593.61,4678.61 v1@600,4685 ; v1@601.64,4690 U8.4@601.64,4725 ; C29.2@2658.61,3792 2658.61,3833.61 2666.64,3841.64 U7.4@2666.64,3880
  Top Layer w25: R5.2@4773.4,3999 4849,3999 v1(4850,4000) v1(5420,4000) ; v1@5479.21,1400 K2.8@5479.21,1501.89 ; v1(5480,1400) 5520.71,1400 D6.1@5660,1539.29 ; P1.5@5490,260 5520,290 5520,601.71 5455.71,666 D4.1@5455.71,790 5791.26,790 C10.2@5800,798.74
  Bottom Layer w25: v1(160,4690) v1(595,4690) 715,4690 915,4890 1200,4890 2105,3985 2520,3985 v1(2660,3845) 2860,3845 3015,3690 3015,3565 3100,3480 4245,3480 4765,4000 v1(4850,4000)
NetC1_1: C1.1 P1.6 P1.7 R1.1 | length 2351.8
  Top Layer w25: P1.6@4024.02,260 4206.5,77.5 5692.5,77.5 5875,260 R1.1@5875,531.6 C1.1@5953.02,531.6
NetC6_2: C6.2 J1.10 J1.11 R2.2 | length 1464.8
  Top Layer w25: J1.11@2708.07,260 2890.57,77.5 3509.43,77.5 J1.10@3691.93,260 3691.93,501.54 3608.06,501.54 R2.2@3605,504.6
NetC11_1: C11.1 J2.26 J2.27 R3.1 | length 2353.2
  Top Layer w25: C11.1@605,526.61 603.8,527.82 523.78,527.82 J2.27@523.78,260 706.28,77.5 2193.72,77.5 J2.26@2376.22,260
NetC12_2: C12.2 R9.1 U1.2 | length 322.1
  Top Layer w10: 4669.69,3419.69 U1.2@4669.69,3467
  Top Layer w12: R9.1@4553,3563.6 C12.2@4553,3488.39 4601.61,3488.39 4610,3480 4610,3415 4625,3400 4650,3400 4669.69,3419.69
NetC13_1: C13.1 R8.1 R12.1 U3.3 | length 1019.8
  Top Layer w12: U3.3@906,1368.36 906,1284 925,1265 R12.1@1105,1265 ; R12.1@1105,1251.4 C13.1@1105,1980
NetC17_2: C17.2 R21.1 U4.2 | length 307
  Top Layer w11: 5170.69,3420.69 U4.2@5170.69,3467
  Top Layer w12: R21.1@5046,3562.6 5045,3561.6 C17.2@5045,3495.39 5089.61,3495.39 5100,3485 5100,3445 5140,3405 5155,3405 5170.69,3420.69
NetC18_1: C18.1 D7.3 D8.1 R20.2 R22.1 | length 3835.8
  Top Layer w12: v1(3935,2355) 3972.4,2392.4 D8.1@4025.71,2392.4 ; D7.3@3961.71,2729 3920.4,2687.69 R22.1@3920.4,2502 R20.2@4023.6,2502 D8.1@4023.6,2394.51
  Bottom Layer w15: C18.1@661,2353 3933,2353 v1(3935,2355)
NetC20_1: C20.1 R28.1 U5.2 | length 1086.3
  Top Layer w12: R28.1@4342,2765.6 4342,2153 4404.39,2090.61 C20.1@4471,2090.61 4471,2014 4495,1990 4610,1990 4626,2006 U5.2@4626,2076.64
NetC20_2: C20.2 R27.1 U5.6 | length 953.2
  Top Layer w12: R27.1@4443,2765.6 4443,2449.92 4396.82,2403.74 4396.82,2241.57 C20.2@4471,2167.39 4483.61,2180 4665,2180 4676,2191 U5.6@4676,2281.36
